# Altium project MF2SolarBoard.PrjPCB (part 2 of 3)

## Sheet DCPower.SchDoc
size B; SheetNumber: 2; nhSheetName: DC Power (PV)
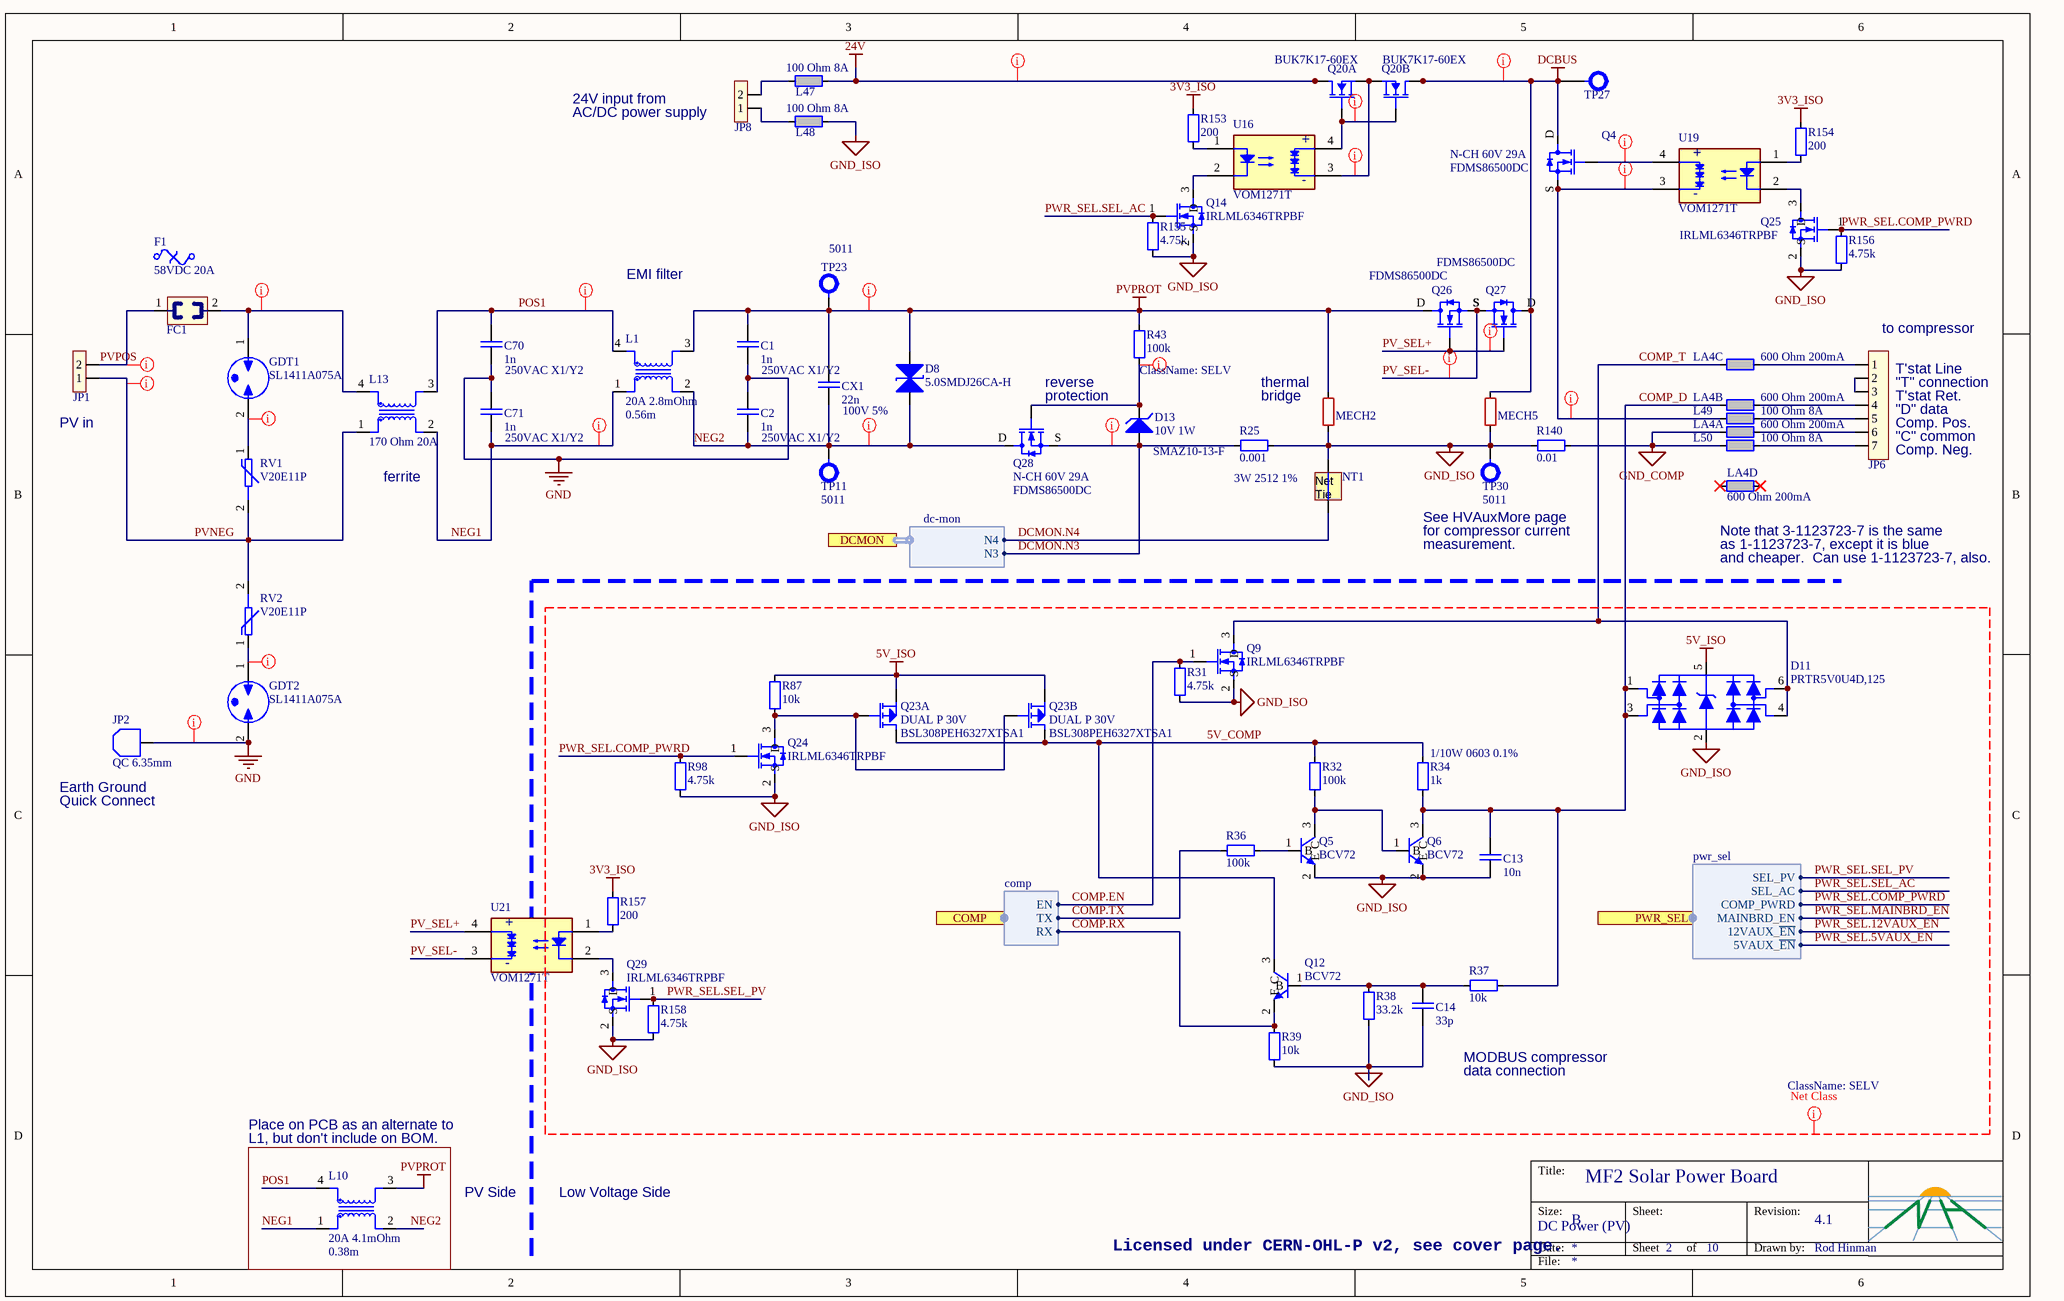
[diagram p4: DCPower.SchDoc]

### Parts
C1  250VAC X1/Y2  value_text: 1n  [CAPC4720X22N]
C2  250VAC X1/Y2  value_text: 1n  [CAPC4720X22N]
C13  value_text: 10n  [CAPC1608X09N[0603]]  (hidden comment: 50V C0G 0603)
C14  value_text: 33p  [CAPC1608X09N[0603]]  (hidden comment: 50V C0G 0603)
C70  250VAC X1/Y2  value_text: 1n  [CAPC4720X22N]
C71  250VAC X1/Y2  value_text: 1n  [CAPC4720X22N]
CX1  100V 5%  value_text: 22n  [CAPC3216X100]
D8  manufacturer_pn: 5.0SMDJ26CA-H  [DO-214AB_SMC_BIDIR]  (hidden comment: TVS)
D11  manufacturer_pn: PRTR5V0U4D,125  [SOT23-6]  (hidden comment: TVS)
D13  10V 1W  manufacturer_pn: SMAZ10-13-F  [DO-214AC]
F1  58VDC 20A  [FUSE_MINI_ATO_20A]  (mechanical)
FC1  MINI  [KEYSTONE_3568]  (value not drawn)
GDT1  manufacturer_pn: SL1411A075A  [LITTELFUSE_SL1411A]  (hidden comment: 75Vdc breakdown)
GDT2  manufacturer_pn: SL1411A075A  [LITTELFUSE_SL1411A]  (hidden comment: 75Vdc breakdown)
JP1  JST VL  [JST_B02P-VL]  (value not drawn)
JP2  QC 6.35mm  [AMP_63849-1]
JP6  1x7 3.96mm blue  [AMP_1-1123723-7]  (value not drawn)
JP8  1x2 3.96mm  [AMP_1-1123723-2]  (value not drawn)
L1  20A 2.8mOhm  value_text: 0.56m  [WURTH_S14100038]
L10  20A 4.1mOhm  value_text: 0.38m  [PULSE_HCCI-80]
L13  170 Ohm 20A  [LAIRD_CM3443Z171R-10]
L47  100 Ohm 8A  [INDC4532X17N[1812]]
L48  100 Ohm 8A  [INDC4532X17N[1812]]
L49  100 Ohm 8A  [INDC4532X17N[1812]]
L50  100 Ohm 8A  [INDC4532X17N[1812]]
LA4  600 Ohm 200mA  [FERCAV80P320X160X70-4]  (parts A,B,C,D of 4)
MECH2  10C/W  [RESC2012X06N[0805]]  (value not drawn)
MECH5  10C/W  [RESC2012X06N[0805]]  (value not drawn)
NT1  Net Tie  [NETTIE1608X05AN[0603]]  (value not drawn)  (net tie, no BOM)
Q4  N-CH 60V 29A  manufacturer_pn: FDMS86500DC  [SOIC-8 PPAK]
Q5  manufacturer_pn: BCV72  [SOT23-3]  (hidden comment: 60V 300mA)
Q6  manufacturer_pn: BCV72  [SOT23-3]  (hidden comment: 60V 300mA)
Q9  manufacturer_pn: IRLML6346TRPBF  [SOT23-3]  (hidden comment: N-CH 30V 3.4A)
Q12  manufacturer_pn: BCV72  [SOT23-3]  (hidden comment: 60V 300mA)
Q14  manufacturer_pn: IRLML6346TRPBF  [SOT23-3]  (hidden comment: N-CH 30V 3.4A)
Q20  manufacturer_pn: BUK7K17-60EX  [SOT1205_LFPAK56D]  (hidden comment: N-CH 60V 30A)  (parts A,B of 2)
Q23  DUAL P 30V  manufacturer_pn: BSL308PEH6327XTSA1  [SOT_23_6]  (parts A,B of 2)
Q24  manufacturer_pn: IRLML6346TRPBF  [SOT23-3]  (hidden comment: N-CH 30V 3.4A)
Q25  manufacturer_pn: IRLML6346TRPBF  [SOT23-3]  (hidden comment: N-CH 30V 3.4A)
Q26  manufacturer_pn: FDMS86500DC  [SOIC-8 PPAK]  (hidden comment: N-CH 60V 29A)
Q27  manufacturer_pn: FDMS86500DC  [SOIC-8 PPAK]  (hidden comment: N-CH 60V 29A)
Q28  N-CH 60V 29A  manufacturer_pn: FDMS86500DC  [SOIC-8 PPAK]
Q29  manufacturer_pn: IRLML6346TRPBF  [SOT23-3]  (hidden comment: N-CH 30V 3.4A)
R25  3W 2512 1%  value_text: 0.001  [RESC6534X70[2512]_mOhm]
R31  value_text: 4.75k  [RESC1608X05AN[0603]]  (hidden comment: 1/10W 0603 1%)
R32  value_text: 100k  [RESC1608X05AN[0603]]  (hidden comment: 1/10W 0603 1%)
R34  1/10W 0603 0.1%  value_text: 1k  [RESC1608X05AN[0603]]
R36  value_text: 100k  [RESC1608X05AN[0603]]  (hidden comment: 1/10W 0603 1%)
R37  value_text: 10k  [RESC1608X05AN[0603]]  (hidden comment: 1/10W 0603 1%)
R38  value_text: 33.2k  [RESC1608X05AN[0603]]  (hidden comment: 1/10W 0603 1%)
R39  value_text: 10k  [RESC1608X05AN[0603]]  (hidden comment: 1/10W 0603 1%)
R43  value_text: 100k  [RESC1608X05AN[0603]]  (hidden comment: 1/10W 0603 1%)
R87  value_text: 10k  [RESC1608X05AN[0603]]  (hidden comment: 1/10W 0603 1%)
R98  value_text: 4.75k  [RESC1608X05AN[0603]]  (hidden comment: 1/10W 0603 1%)
R140  value_text: 0.01  [RESC6534X70[2512]]  (hidden comment: 3W 2512 1%)
R153  value_text: 200  [RESC1608X05AN[0603]]  (hidden comment: 1/10W 0603 1%)
R154  value_text: 200  [RESC1608X05AN[0603]]  (hidden comment: 1/10W 0603 1%)
R155  value_text: 4.75k  [RESC1608X05AN[0603]]  (hidden comment: 1/10W 0603 1%)
R156  value_text: 4.75k  [RESC1608X05AN[0603]]  (hidden comment: 1/10W 0603 1%)
R157  value_text: 200  [RESC1608X05AN[0603]]  (hidden comment: 1/10W 0603 1%)
R158  value_text: 4.75k  [RESC1608X05AN[0603]]  (hidden comment: 1/10W 0603 1%)
RV1  manufacturer_pn: V20E11P  [LITTELFUSE_ULTRAMOV_20MM]  (hidden comment: 11VAC 14VDC MWV)
RV2  manufacturer_pn: V20E11P  [LITTELFUSE_ULTRAMOV_20MM]  (hidden comment: 11VAC 14VDC MWV)
TP11  manufacturer_pn: 5011  [KEYSTONE_5011]  (hidden comment: TP BLK)
TP23  manufacturer_pn: 5011  [KEYSTONE_5011]  (hidden comment: TP BLK)
TP27  TP TH  0.78mm  [TP_TH078H127P]  (value not drawn)  (no BOM)
TP30  manufacturer_pn: 5011  [KEYSTONE_5011]  (hidden comment: TP BLK)
U16  manufacturer_pn: VOM1271T  [VISHAY_SOP-4]  (hidden comment: PV Out)
U19  manufacturer_pn: VOM1271T  [VISHAY_SOP-4]  (hidden comment: PV Out)
U21  manufacturer_pn: VOM1271T  [VISHAY_SOP-4]  (hidden comment: PV Out)

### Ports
COMP (harness comp), DCMON (harness dc-mon), PWR_SEL (harness pwr_sel)

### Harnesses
comp: TX, RX, EN
dc-mon: N4, N3
pwr_sel: SEL_PV, SEL_AC, COMP_PWRD, 12VAUX_~{EN}, 5VAUX_~{EN}, MAINBRD_EN

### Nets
3V3_ISO: R153.2 R154.2 R157.2
5V_ISO: D11.5(VCC) Q23.2(S2) Q23.5(S1) R87.2
24V: L47.1 Q20.7(D1) Q20.8(D1)
DCBUS: MECH5.1 Q4.D Q20.5(D2) Q20.6(D2) Q27.D TP27.1
GND: C1.2 C2.1 C70.2 C71.1 GDT2.2 JP2.1
GND_COMP: L50.1 LA4.1 R140.2
GND_ISO: C13.2 C14.2 D11.2(GND) L48.1 MECH2.2 MECH5.2 NT1.2 Q5.2(E) Q6.2(E) Q9.2(S) Q14.2(S) Q24.2(S) Q25.2(S) Q29.2(S) R25.2 R31.2 R38.2 R39.2 R98.2 R140.1 R155.1 R156.1 R158.1 TP30.1
PVPROT: C1.1 CX1.1 D8.2 L1.3 L10.3 MECH2.1 Q26.D R43.2 TP23.1
5V_COMP: Q12.3(C) Q23.4(D2) Q23.6(D1) R32.1 R34.1
COMP.EN: Q9.1(G) R31.1 ; port COMP.EN
COMP.RX: Q12.2(E) R39.1 ; port COMP.RX
COMP.TX: R36.1 ; port COMP.TX
COMP_D: C13.1 D11.1(IO1) D11.3(IO2) LA4.2 Q6.3(C) R34.2 R37.2
COMP_T: D11.4(IO3) D11.6(IO4) LA4.3 Q9.3(D)
DCMON.N3: D13.A Q28.S R25.1 ; port DCMON.N3
DCMON.N4: NT1.1 ; port DCMON.N4
NEG1: C71.2 L1.1 L10.1 L13.2
NEG2: C2.2 CX1.2 D8.1 L1.2 L10.2 Q28.D TP11.1
POS1: C70.1 L1.4 L10.4 L13.3
PV_SEL+: Q26.G Q27.G U21.4(+)
PV_SEL-: Q26.S Q27.S U21.3(-)
PVNEG: JP1.1 L13.1 RV1.2 RV2.2
PVPOS: FC1.1 JP1.2
PWR_SEL.COMP_PWRD: Q24.1(G) Q25.1(G) R98.1 R156.2 ; port PWR_SEL.COMP_PWRD
PWR_SEL.SEL_AC: Q14.1(G) R155.2 ; port PWR_SEL.SEL_AC
PWR_SEL.SEL_PV: Q29.1(G) R158.2 ; port PWR_SEL.SEL_PV
NetC14_1: C14.1 Q12.1(B) R37.1 R38.1
NetD13_K: D13.K Q28.G R43.1
NetFC1_2: FC1.2 GDT1.1 L13.4
NetGDT1_2: GDT1.2 RV1.1
NetGDT2_1: GDT2.1 RV2.1
NetJP6_1: JP6.1 LA4.6
NetJP6_2: JP6.2 JP6.3
NetJP6_4: JP6.4 LA4.7
NetJP6_5: JP6.5 L49.2
NetJP6_6: JP6.6 LA4.8
NetJP6_7: JP6.7 L50.2
NetJP8_1: JP8.1 L48.2
NetJP8_2: JP8.2 L47.2
NetL49_1: L49.1 Q4.S U19.3(-)
NetQ4_G: Q4.G U19.4(+)
NetQ5_1: Q5.1(B) R36.2
NetQ5_3: Q5.3(C) Q6.1(B) R32.2
NetQ14_3: Q14.3(D) U16.2(Cathode)
NetQ20_1: Q20.1(S1) Q20.3(S2) U16.3(-)
NetQ20_2: Q20.2(G1) Q20.4(G2) U16.4(+)
NetQ23_1: Q23.1(G1) Q23.3(G2) Q24.3(D) R87.1
NetQ25_3: Q25.3(D) U19.2(Cathode)
NetQ29_3: Q29.3(D) U21.2(Cathode)
NetR153_1: R153.1 U16.1(Anode)
NetR154_1: R154.1 U19.1(Anode)
NetR157_1: R157.1 U21.1(Anode)

Not connected (* = marked no-connect by the designer): LA4 4* 5*

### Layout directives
net class PVPOS: 24V, DCBUS, NetFC1_2, NetGDT1_2, NetL49_1, NetQ4_G, NetQ20_1, NetQ20_2, POS1, PV_SEL+, PV_SEL-, PVPOS, PVPROT
net class SELV: 3V3_ISO, 5V_COMP, 5V_ISO, COMP.EN, COMP.RX, COMP.TX, DCMON.N3, GND_ISO, NEG1, NEG2, NetD13_K, NetGDT2_1, PVNEG, PWR_SEL.5VAUX_~{EN}, PWR_SEL.12VAUX_~{EN}, PWR_SEL.COMP_PWRD, PWR_SEL.MAINBRD_EN, PWR_SEL.SEL_AC, PWR_SEL.SEL_PV
net class Earth: GND

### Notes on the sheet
- 24V input from
- (near JP8) AC/DC power supply
- EMI filter
- (near JP6) to compressor
- (near JP6) T'stat Line
- (near JP1) PV in
- (near Q28) reverse
- (near Q28) protection
- (near MECH2) thermal
- (near MECH2) bridge
- (near JP6) T'stat Ret.
- (near JP6) Comp. Pos.
- (near JP6) "C" common
- (near JP6) "T" connection
- (near JP6) "D" data
- (near L13) ferrite
- (near JP6) Comp. Neg.
- See HVAuxMore page
- for compressor current
- measurement.
- (near LA4) Note that 3-1123723-7 is the same
- (near LA4) as 1-1123723-7, except it is blue
- and cheaper.  Can use 1-1123723-7, also.
- (near JP2) Earth Ground
- (near JP2) Quick Connect
- MODBUS compressor
- data connection
- Place on PCB as an alternate to
- (near L10) L1, but don't include on BOM.
- PV Side
- Low Voltage Side
- Licensed under CERN-OHL-P v2, see cover page.

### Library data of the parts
C1 C2 C70 C71 = CAP-00055: CAP CER 1000PF 250VAC X7R 1808; manufacturer: Johanson Dielectrics Inc.; manufacturer_pn: 502R29W102KV3E-****-SC; id: 148102; value: 1E-9; Key Parameters: X1/Y2 rating required
C13 = CAP-00027: 10000pF 50V Ceramic Capacitor C0G, NP0 0603 (1608 Metric) 0.063" L x 0.031" W (1.60mm x 0.80mm); manufacturer: Murata Electronics North America; manufacturer_pn: GRM1885C1H103JA01D; id: 137118; value: 1E-8; Key Parameters: V >= 6.3V
C14 = CAP-00043: 33pF 50V Ceramic Capacitor C0G, NP0 0603 (1608 Metric) 0.063" L x 0.031" W (1.60mm x 0.80mm); manufacturer: Murata Electronics North America; manufacturer_pn: GRM1885C1H330JA01D; id: 140735; value: 3.3E-11; Key Parameters: v >= 6.3V
CX1 = CAP-00054: CAP CER 0.022UF 100V X7R 1206; manufacturer: Kemet; manufacturer_pn: C1206C223J1RACTU; id: 148096; value: 2.2E-8
D8 = DIO-00038: TVS DIODE 26VWM 42.1VC SMD; manufacturer: Bourns Inc.; id: 193256
D11 = DIO-00000: TVS DIODE 6TSOP; manufacturer: Nexperia USA Inc.; id: 136479
D13 = DIO-00010: Zener Diode 10V 1W ±5% Surface Mount SMA; manufacturer: Diodes Incorporated; id: 137140
F1 = FUSE-00009: FUSE AUTO 20A 58VDC BLADE MINI; manufacturer_pn: 0997020.WXN; manufacturer: Littelfuse Inc.; id: 169759
FC1 = CONN-00117: FUSE HOLDER BLADE 500V 20A PCB; manufacturer_pn: 3568; manufacturer: Keystone Electronics; id: 169758
GDT1 GDT2 = PROT-00004: GDT 75V 10KA THROUGH HOLE; manufacturer: Littelfuse Inc.; id: 147370; value: 75
JP1 = CONN-00118: 2 Positions Header Connector 0.244" (6.20mm) Through Hole Tin; manufacturer_pn: B02P-VL; manufacturer: JST Sales America Inc.; id: 170439
JP2 = CONN-00071: 0.250" (6.35mm) Quick Connect Male Solder Connector Non-Insulated; manufacturer: TE Connectivity AMP Connectors; manufacturer_pn: 63849-1; id: 140464
JP6 = CONN-00087: 7 Positions Header, Unshrouded Connector 0.156" (3.96mm) Through Hole Tin; manufacturer: TE Connectivity AMP Connectors; manufacturer_pn: 3-1123723-7; id: 147885
JP8 = CONN-00067: 2 Positions Header, Unshrouded Connector 0.156" (3.96mm) Through Hole Tin (blue); manufacturer_pn: 3-1123723-2; manufacturer: TE Connectivity AMP Connectors; id: 140460
L1 = IND-00021: 560µH @ 10kHz 2 Line Common Mode Choke Through Hole 20A DCR 2.8 mOhm; manufacturer: Wurth Electronics Inc; manufacturer_pn: S14100038; id: 169932; value: 0.00056
L10 = IND-00022: 2 Line Common Mode Choke Surface Mount 20A DCR 4.1 mOhm; manufacturer_pn: PG1265NL; manufacturer: Pulse Electronics Corporation; id: 169933; value: 0.00038
L13 = FER-00010: 2 Line Common Mode Choke Surface Mount 170 Ohm @ 100MHz 20A DCR 1 mOhm; manufacturer: Laird Technologies EMI; manufacturer_pn: CM3440Z171R-10; value_text: 170; id: 169934; value: 170
L47-L50 = FER-00011: FERRITE BEAD 100 OHM 1812 1LN 10mohm; manufacturer_pn: HI1812V101R-10; manufacturer: Laird Technologies EMI; value_text: 100; id: 169937; value: 100
LA4 = FER-00009: FERRITE BEAD 600 OHM 1206 4LN; manufacturer_pn: BK32164S601-T; manufacturer: Taiyo Yuden; id: 162218; value: 600
MECH2 MECH5 = MECH-00031: Heat Sink Aluminum Nitride Ceramic Heat Spreader Q-Bridge; manufacturer_pn: QB0805A40WYTD; manufacturer: American Technical Ceramics; id: 197164
NT1 = NOBOM-00005: Net tie 0603; manufacturer: New Horizons; id: 137435
Q4 Q26-Q28 = FET-00018: N-Channel 60V 29A (Ta), 108A (Tc) 3.2W (Ta), 125W (Tc) Surface Mount Dual Cool™56; manufacturer: ON Semiconductor; id: 193254
Q5 Q6 Q12 = BJT-00001: Bipolar (BJT) Transistor NPN 60V 500mA 350mW Surface Mount SOT-23-3; manufacturer: ON Semiconductor; id: 145546
Q9 Q14 Q24 Q25 Q29 = FET-00002: MOSFET N-CH 30V 3.4A SOT23; manufacturer: Infineon Technologies; id: 137229
Q20 = FET-00017: Mosfet Array 2 N-Channel (Dual) 60V 30A 53W Surface Mount LFPAK56D; manufacturer: Nexperia USA Inc.; id: 193253
Q23 = FET-00023: Mosfet Array 2 P-Channel (Dual) 30V 2A 500mW Surface Mount PG-TSOP-6-6; manufacturer: Infineon Technologies; id: 297421
R25 = RES-00044: RES SMD 0.001 OHM 1% 3W 2512; manufacturer: Bourns Inc.; manufacturer_pn: CRE2512-FZ-R001E-3; id: 138477; value: 0.001
R31 R98 R155 R156 R158 = RES-00013: RES SMD 4.75K OHM 1% 1/10W 0603; manufacturer_pn: ERJ-3EKF4751V; manufacturer: Panasonic Electronic Components; id: 137091; value: 4750; Key Parameters: 5% OK
R32 = RES-00112: 100 kOhms ±1% 0.1W, 1/10W Chip Resistor 0603 (1608 Metric) Automotive AEC-Q200 Thick Film; manufacturer_pn: ERJ-3EKF1003V; manufacturer: Panasonic Electronic Components; id: 185358; value: 100000; Key Parameters: 1% required for R195.  5% OK for others.
R34 = RES-00067: RES SMD 1KOHM 0.1% 1/10W 0603; manufacturer_pn: ERA-3AEB102V; manufacturer: Panasonic Electronic Components; id: 147997; value: 1000; Key Parameters: 0.1% required
R36 R43 = RES-00112: 100 kOhms ±1% 0.1W, 1/10W Chip Resistor 0603 (1608 Metric) Automotive AEC-Q200 Thick Film; manufacturer_pn: ERJ-3EKF1003V; manufacturer: Panasonic Electronic Components; id: 185358; value: 100000; Key Parameters: 1% required
R37 R39 = RES-00107: 10 kOhms ±1% 0.1W, 1/10W Chip Resistor 0603 (1608 Metric) Automotive AEC-Q200 Thick Film; manufacturer_pn: ERJ-3EKF1002V; manufacturer: Panasonic Electronic Components; id: 182861; value: 10000; Key Parameters: 1% required
R38 = RES-00027: RES SMD 33.2K OHM 1% 1/10W 0603; manufacturer_pn: ERJ-3EKF3322V; manufacturer: Panasonic Electronic Components; id: 137105; value: 33200; Key Parameters: 5% OK
R87 = RES-00107: 10 kOhms ±1% 0.1W, 1/10W Chip Resistor 0603 (1608 Metric) Automotive AEC-Q200 Thick Film; manufacturer: Panasonic Electronic Components; manufacturer_pn: ERJ-3EKF1002V; id: 182861; value: 10000; Key Parameters: 1% required
R140 = RES-00036: RES SMD 0.01 OHM 1% 3W 2512; manufacturer_pn: CRA2512-FZ-R010ELF; manufacturer: Bourns Inc.; id: 137235; value: 0.01; Key Parameters: 1% required
R153 R154 R157 = RES-00019: RES SMD 200 OHM 1% 1/10W 0603; manufacturer_pn: ERJ-3EKF2000V; manufacturer: Panasonic Electronic Components; id: 137097; value: 200; Key Parameters: 5% OK
RV1 RV2 = PROT-00005: VARISTOR 18V 8KA DISC 20MM; manufacturer: Littelfuse Inc.; id: 147371; value: 11
TP11 TP23 TP30 = CONN-00028: TEST POINT PC MULTI PURPOSE BLK; manufacturer: Keystone Electronics; id: 137441
TP27 = NOBOM-00007: Test point, TH, 0.78mm (30mil) hole, 1.27mm (50 mil) pad; manufacturer: New Horizons; id: 137437
U16 U19 U21 = ICXCV-00017: Optoisolator Photovoltaic Output 4500Vrms 1 Channel 4-SOP (2.54mm); manufacturer: Vishay Semiconductor Opto Division; id: 171983

## Sheet ACProtection.SchDoc
size B; SheetNumber: 5; nhSheetName: AC Protection Ctl
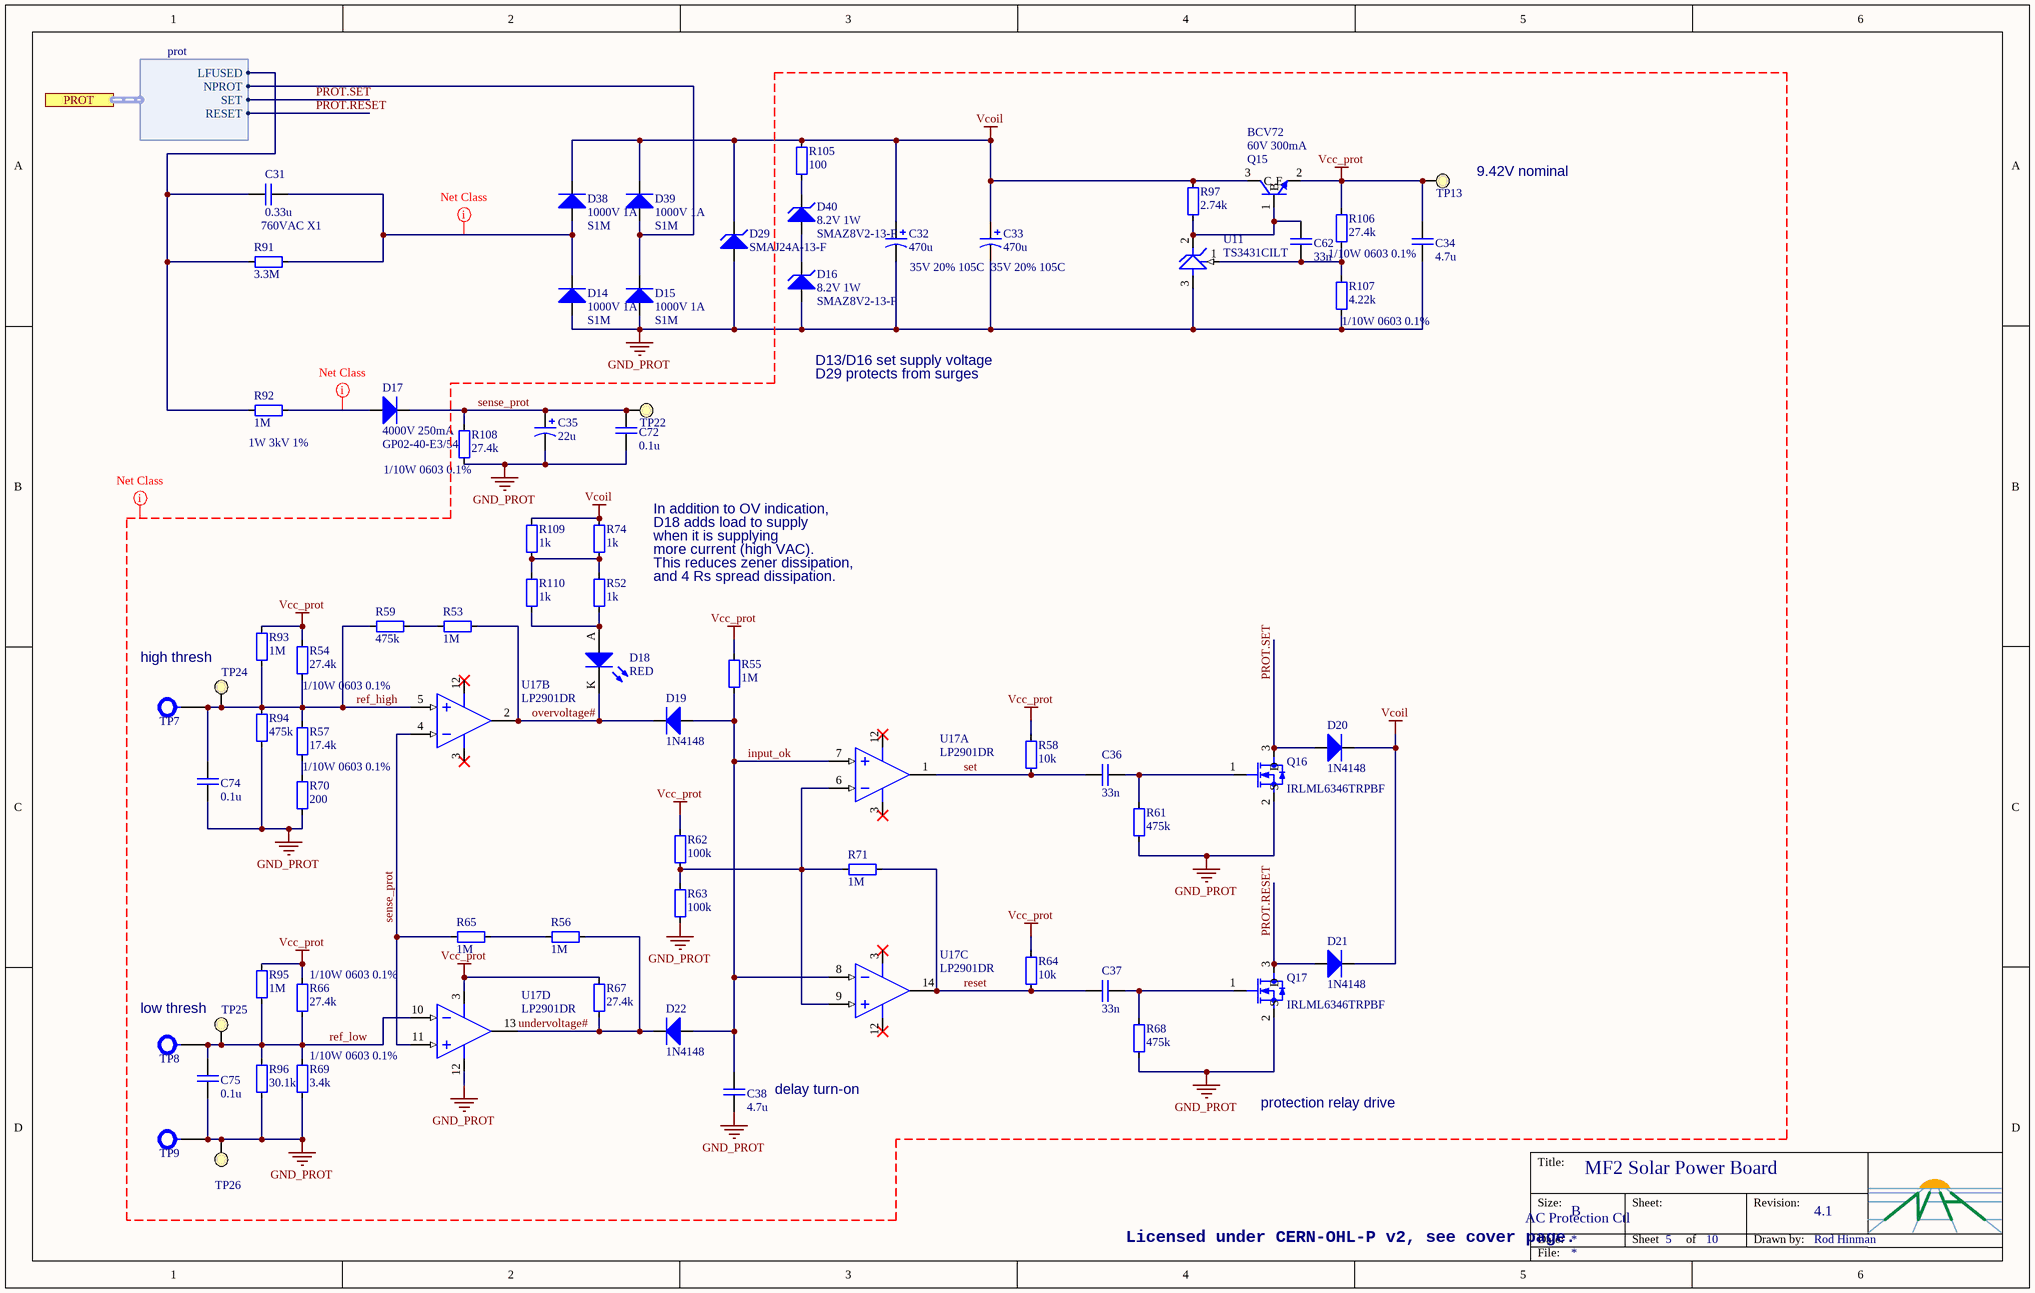
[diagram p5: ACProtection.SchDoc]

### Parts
C31  760VAC X1  value_text: 0.33u  [KEMET_PHE845VF6330MR06L2]
C32  35V 20% 105C  value_text: 470u  [CAP_RB5/10MMX20MM]
C33  35V 20% 105C  value_text: 470u  [CAP_RB5/10MMX20MM]
C34  value_text: 4.7u  [CAPC1608X09N[0603]]  (hidden comment: 25V X6S 0603)
C35  value_text: 22u  [CAP_ALUM_SIZE-SVPF-B6]  (hidden comment: 35V 20% 1 ohm)
C36  value_text: 33n  [CAPC1608X09N[0603]]  (hidden comment: 50V X7R 0603)
C37  value_text: 33n  [CAPC1608X09N[0603]]  (hidden comment: 50V X7R 0603)
C38  value_text: 4.7u  [CAPC1608X09N[0603]]  (hidden comment: 25V X6S 0603)
C62  value_text: 33n  [CAPC1608X09N[0603]]  (hidden comment: 50V X7R 0603)
C72  value_text: 0.1u  [CAPC1608X09N[0603]]  (hidden comment: 50V X7R 0603)
C74  value_text: 0.1u  [CAPC1608X09N[0603]]  (hidden comment: 50V X7R 0603)
C75  value_text: 0.1u  [CAPC1608X09N[0603]]  (hidden comment: 50V X7R 0603)
D14  1000V 1A  manufacturer_pn: S1M  [DO-214AC]
D15  1000V 1A  manufacturer_pn: S1M  [DO-214AC]
D16  8.2V 1W  manufacturer_pn: SMAZ8V2-13-F  [DO-214AC]
D17  4000V 250mA  manufacturer_pn: GP02-40-E3/54  [DO-204AL[DO-41]]
D18  RED  [LEDC1608X06NRED,0603,]
D19  1N4148  [SOD-123]
D20  1N4148  [SOD-123]
D21  1N4148  [SOD-123]
D22  1N4148  [SOD-123]
D29  manufacturer_pn: SMAJ24A-13-F  [DO-214AC]  (hidden comment: 24WVM)
D38  1000V 1A  manufacturer_pn: S1M  [DO-214AC]
D39  1000V 1A  manufacturer_pn: S1M  [DO-214AC]
D40  8.2V 1W  manufacturer_pn: SMAZ8V2-13-F  [DO-214AC]
Q15  60V 300mA  manufacturer_pn: BCV72  [SOT23-3]
Q16  manufacturer_pn: IRLML6346TRPBF  [SOT23-3]  (hidden comment: N-CH 30V 3.4A)
Q17  manufacturer_pn: IRLML6346TRPBF  [SOT23-3]  (hidden comment: N-CH 30V 3.4A)
R52  value_text: 1k  [RESC1608X05AN[0603]]  (hidden comment: 1/10W 0603 1%)
R53  value_text: 1M  [RESC1608X05AN[0603]]  (hidden comment: 1/10W 0603 1%)
R54  1/10W 0603 0.1%  value_text: 27.4k  [RESC1608X05AN[0603]]
R55  value_text: 1M  [RESC1608X05AN[0603]]  (hidden comment: 1/10W 0603 1%)
R56  value_text: 1M  [RESC1608X05AN[0603]]  (hidden comment: 1/10W 0603 1%)
R57  1/10W 0603 0.1%  value_text: 17.4k  [RESC1608X05AN[0603]]
R58  value_text: 10k  [RESC1608X05AN[0603]]  (hidden comment: 1/10W 0603 1%)
R59  value_text: 475k  [RESC1608X05AN[0603]]  (hidden comment: 1/10W 0603 1%)
R61  value_text: 475k  [RESC1608X05AN[0603]]  (hidden comment: 1/10W 0603 1%)
R62  value_text: 100k  [RESC1608X05AN[0603]]  (hidden comment: 1/10W 0603 1%)
R63  value_text: 100k  [RESC1608X05AN[0603]]  (hidden comment: 1/10W 0603 1%)
R64  value_text: 10k  [RESC1608X05AN[0603]]  (hidden comment: 1/10W 0603 1%)
R65  value_text: 1M  [RESC1608X05AN[0603]]  (hidden comment: 1/10W 0603 1%)
R66  1/10W 0603 0.1%  value_text: 27.4k  [RESC1608X05AN[0603]]
R67  value_text: 27.4k  [RESC1608X05AN[0603]]  (hidden comment: 1/10W 0603 0.1%)
R68  value_text: 475k  [RESC1608X05AN[0603]]  (hidden comment: 1/10W 0603 1%)
R69  1/10W 0603 0.1%  value_text: 3.4k  [RESC1608X05AN[0603]]
R70  value_text: 200  [RESC1608X05AN[0603]]  (hidden comment: 1/10W 0603 1%)
R71  value_text: 1M  [RESC1608X05AN[0603]]  (hidden comment: 1/10W 0603 1%)
R74  value_text: 1k  [RESC1608X05AN[0603]]  (hidden comment: 1/10W 0603 1%)
R91  value_text: 3.3M  [RESC5025X60,2010,]  (hidden comment: 0.5W 2010 1%)
R92  1W 3kV 1%  value_text: 1M  [RESC6534X70[2512]]
R93  value_text: 1M  [RESC1608X05AN[0603]]  (hidden comment: 1/10W 0603 1%)
R94  value_text: 475k  [RESC1608X05AN[0603]]  (hidden comment: 1/10W 0603 1%)
R95  value_text: 1M  [RESC1608X05AN[0603]]  (hidden comment: 1/10W 0603 1%)
R96  value_text: 30.1k  [RESC1608X05AN[0603]]  (hidden comment: 1/10W 0603 1%)
R97  value_text: 2.74k  [RESC1608X05AN[0603]]  (hidden comment: 1/10W 0603 1%)
R105  value_text: 100  [RESC6534X70[2512]]  (hidden comment: 1W 2512 5%)
R106  1/10W 0603 0.1%  value_text: 27.4k  [RESC1608X05AN[0603]]
R107  1/10W 0603 0.1%  value_text: 4.22k  [RESC1608X05AN[0603]]
R108  1/10W 0603 0.1%  value_text: 27.4k  [RESC1608X05AN[0603]]
R109  value_text: 1k  [RESC1608X05AN[0603]]  (hidden comment: 1/10W 0603 1%)
R110  value_text: 1k  [RESC1608X05AN[0603]]  (hidden comment: 1/10W 0603 1%)
TP7  TP TH  0.78mm  [TP_TH078H127P]  (value not drawn)  (no BOM)
TP8  TP TH  0.78mm  [TP_TH078H127P]  (value not drawn)  (no BOM)
TP9  TP TH  0.78mm  [TP_TH078H127P]  (value not drawn)  (no BOM)
TP13  TP SMD 1.5mm  [TP_SMD_Ø1.5mm]  (value not drawn)  (no BOM)
TP22  TP SMD 1.5mm  [TP_SMD_Ø1.5mm]  (value not drawn)  (no BOM)
TP24  TP SMD 1.5mm  [TP_SMD_Ø1.5mm]  (value not drawn)  (no BOM)
TP25  TP SMD 1.5mm  [TP_SMD_Ø1.5mm]  (value not drawn)  (no BOM)
TP26  TP SMD 1.5mm  [TP_SMD_Ø1.5mm]  (value not drawn)  (no BOM)
U11  manufacturer_pn: TS3431CILT  [SOT_23_3]  (hidden comment: TS3431)
U17  LP2901DR  [SOIC-14]  (parts A,B,C,D of 4)

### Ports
PROT (harness prot)

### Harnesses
prot: LFUSED, NPROT, SET, RESET

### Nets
GND_PROT: C32.- C33.- C34.2 C35.- C38.2 C72.2 C74.2 C75.2 D14.A D15.A D16.A D29.A Q16.2(S) Q17.2(S) R61.1 R63.1 R68.1 R69.2 R70.2 R94.2 R96.2 R107.2 R108.2 TP9.1 TP26.1 U11.3(A) U17.12(V-)
Vcc_prot: C34.1 Q15.2(E) R54.1 R55.2 R58.2 R62.2 R64.2 R66.1 R67.2 R93.1 R95.1 R106.1 TP13.1 U17.3(V+)
Vcoil: C32.+ C33.+ D20.K D21.K D29.K D38.K D39.K Q15.3(C) R74.2 R97.2 R105.1 R109.2
input_ok: C38.1 D19.A D22.A R55.1 U17.7(IN1+) U17.8(IN3-)
overvoltage#: D18.K D19.K R53.1 U17.2(OUT2)
PROT.LFUSED: C31.1 R91.1 R92.1 ; port PROT.LFUSED
PROT.NPROT: D15.K D39.A ; port PROT.NPROT
PROT.RESET: D21.A Q17.3(D) ; port PROT.RESET
PROT.SET: D20.A Q16.3(D) ; port PROT.SET
ref_high: C74.1 R54.2 R57.2 R59.2 R93.2 R94.1 TP7.1 TP24.1 U17.5(IN2+)
ref_low: C75.1 R66.2 R69.1 R95.2 R96.1 TP8.1 TP25.1 U17.10(IN4-)
reset: C37.2 R64.1 R71.1 U17.14(OUT3)
sense_prot: C35.+ C72.1 D17.K R65.2 R108.1 TP22.1 U17.4(IN2-) U17.11(IN4+)
set: C36.2 R58.1 U17.1(OUT1)
undervoltage#: D22.K R56.1 R67.1 U17.13(OUT4)
NetC31_2: C31.2 D14.K D38.A R91.2
NetC36_1: C36.1 Q16.1(G) R61.2
NetC37_1: C37.1 Q17.1(G) R68.2
NetC62_1: C62.1 Q15.1(B) R97.1 U11.2(K)
NetC62_2: C62.2 R106.2 R107.1 U11.1(VREF)
NetD16_K: D16.K D40.A
NetD17_A: D17.A R92.2
NetD18_A: D18.A R52.1 R110.1
NetD40_K: D40.K R105.2
NetR52_2: R52.2 R74.1 R109.1 R110.2
NetR53_2: R53.2 R59.1
NetR56_2: R56.2 R65.1
NetR57_1: R57.1 R70.1
NetR62_1: R62.1 R63.2 R71.2 U17.6(IN1-) U17.9(IN3+)

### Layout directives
net class ProtCtrl: GND_PROT, input_ok, NetC31_2, overvoltage#, PROT.RESET, PROT.SET, ref_high, ref_low, reset, sense_prot, set, undervoltage#, Vcc_prot, Vcoil
net class LineUnprot: NetD17_A

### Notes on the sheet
- (near TP13) 9.42V nominal
- D13/D16 set supply voltage
- D29 protects from surges
- D18 adds load to supply
- when it is supplying
- more current (high VAC).
- This reduces zener dissipation,
- In addition to OV indication,
- and 4 Rs spread dissipation.
- high thresh
- low thresh
- delay turn-on
- protection relay drive
- Licensed under CERN-OHL-P v2, see cover page.

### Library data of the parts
C31 = CAP-00039: 0.33µF Film Capacitor 760V 1500V (1.5kV) Polypropylene (PP), Metallized Radial 1.240" L x 0.748" W (31.50mm x 19.00mm); manufacturer: Kemet; manufacturer_pn: PHE845VF6330MR06L2; id: 139964; value: 3.3E-7; Key Parameters: X1 rating required
C32 C33 = CAP-00032: 470µF 35V Aluminum Capacitors Radial, Can 2000 Hrs @ 105°C; manufacturer: Kemet; manufacturer_pn: ESH477M035AH3AA; id: 137131; value: 0.00047; Key Parameters: V >= 35V
C34 C38 = CAP-00015: 4.7µF 25V Ceramic Capacitor X6S 0603 (1608 Metric) 0.063" L x 0.031" W (1.60mm x 0.80mm); manufacturer: Murata Electronics North America; manufacturer_pn: GRM188C81E475KE11D; id: 136726; value: 4.7E-6; Key Parameters: V >= 16V
C35 = CAP-00073: 22µF 35V Aluminum Electrolytic Capacitors Radial, Can - SMD 1 Ohm @ 100kHz 2000 Hrs @ 105°C; manufacturer: Kemet; manufacturer_pn: EEV226M035A9DAA; id: 171406; value: 2.2E-5; Key Parameters: V >= 35V
C36 C37 C62 = CAP-00000: 0.033µF 50V Ceramic Capacitor X7R 0603 (1608 Metric) 0.063" L x 0.031" W (1.60mm x 0.80mm); manufacturer: Murata Electronics North America; manufacturer_pn: GRM188R71H333KA61D; id: 136460; value: 3.3E-8; Key Parameters: V >= 16V
C72 C74 C75 = CAP-00001: 0.10µF 50V Ceramic Capacitor X7R 0603 (1608 Metric) 0.063" L x 0.031" W (1.60mm x 0.80mm); manufacturer: Murata Electronics North America; manufacturer_pn: GRM188R71H104KA93D; id: 136482; value: 1E-7; Key Parameters: V >= 25V
D14 D15 D38 D39 = DIO-00009: Diode Standard 1000V (1kV) 1A Surface Mount SMA (DO-214AC); manufacturer: Fairchild Semiconductor; id: 137139
D16 D40 = DIO-00017: Zener Diode 8.2V 1W ±5% Surface Mount SMA; manufacturer: Diodes Incorporated; id: 141314
D17 = DIO-00011: Diode Standard 4000V (4kV) 250mA Through Hole DO-204AL (DO-41); manufacturer: Vishay Semiconductor Diodes Division; id: 137141
D18 = LED-00005: Red 633nm LED Indication - Discrete 2V 0603 (1608 Metric) 28mcd min, 104mcd typ., diffused; manufacturer: OSRAM Opto Semiconductors Inc.; manufacturer_pn: LS Q976-NR-1; id: 137518
D19-D22 = DIO-00004: Diode Standard 100V 150mA Surface Mount SOD-123; manufacturer_pn: 1N4148W-TP; manufacturer: Micro Commercial Co; id: 137134
D29 = DIO-00018: TVS DIODE 24VWM 38.9VC SMA; manufacturer: Diodes Incorporated; id: 145545
Q15 = BJT-00001: as Q5 on sheet DCPower
Q16 Q17 = FET-00002: as Q9 on sheet DCPower
R52 R74 R109 R110 = RES-00113: 1 kOhms ±1% 0.1W, 1/10W Chip Resistor 0603 (1608 Metric) Automotive AEC-Q200 Thick Film; manufacturer: Panasonic Electronic Components; manufacturer_pn: ERJ-3EKF1001V; id: 185365; value: 1000; Key Parameters: 1% required
R53 R55 R56 R65 R71 = RES-00114: 1 MOhms ±1% 0.1W, 1/10W Chip Resistor 0603 (1608 Metric) Automotive AEC-Q200 Thick Film; manufacturer: Panasonic Electronic Components; manufacturer_pn: ERJ-3EKF1004V; id: 185423; value: 1000000; Key Parameters: 5% OK
R54 R66 R67 R106 R108 = RES-00051: RES SMD 27.4KOHM 0.1% 1/10W 0603; manufacturer: Panasonic Electronic Components; manufacturer_pn: ERA-3AEB2742V; id: 141324; value: 27400; Key Parameters: 0.1% required
R57 = RES-00057: 17.4k Ohm ±0.1% 0.1W, 1/10W Chip Resistor 0603 (1608 Metric) Moisture Resistant Thin Film; manufacturer: Yageo; manufacturer_pn: RT0603BRD0717K4L; id: 145543; value: 17400; Key Parameters: 0.1% required
R58 R64 = RES-00107: as R87 on sheet DCPower
R59 R61 R68 = RES-00032: RES SMD 475K OHM 1% 1/10W 0603; manufacturer: Panasonic Electronic Components; manufacturer_pn: ERJ-3EKF4753V; id: 137110; value: 475000; Key Parameters: 1% required
R62 R63 = RES-00112: 100 kOhms ±1% 0.1W, 1/10W Chip Resistor 0603 (1608 Metric) Automotive AEC-Q200 Thick Film; manufacturer: Panasonic Electronic Components; manufacturer_pn: ERJ-3EKF1003V; id: 185358; value: 100000; Key Parameters: 1% required
R69 = RES-00056: 3.4k Ohm ±0.1% 0.1W, 1/10W Chip Resistor 0603 (1608 Metric) Moisture Resistant Thin Film; manufacturer: Yageo; manufacturer_pn: RT0603BRD073K4L; id: 145542; value: 3400; Key Parameters: 0.1% required
R70 = RES-00019: RES SMD 200 OHM 1% 1/10W 0603; manufacturer: Panasonic Electronic Components; manufacturer_pn: ERJ-3EKF2000V; id: 137097; value: 200; Key Parameters: 5% OK
R91 = RES-00125: 3.3 MOhms ±1% 0.5W, 1/2W Chip Resistor 2010 (5025 Metric) High Voltage Thick Film; manufacturer: Bourns Inc.; manufacturer_pn: CHV2010-FX-3304ELF; id: 192299; value: 3300000; Key Parameters: 1% required
R92 = RES-00150: 1 MOhms ±1% 1W Chip Resistor Nonstandard High Voltage Thick Film; manufacturer: Bourns Inc.; manufacturer_pn: CHV2512-FX-1004ELF; id: 245406; value: 1000000; Key Parameters: 1% required
R93 R95 = RES-00114: 1 MOhms ±1% 0.1W, 1/10W Chip Resistor 0603 (1608 Metric) Automotive AEC-Q200 Thick Film; manufacturer_pn: ERJ-3EKF1004V; manufacturer: Panasonic Electronic Components; id: 185423; value: 1000000; Key Parameters: 5% OK
R94 = RES-00032: RES SMD 475K OHM 1% 1/10W 0603; manufacturer_pn: ERJ-3EKF4753V; manufacturer: Panasonic Electronic Components; id: 137110; value: 475000; Key Parameters: 1% required
R96 = RES-00026: RES SMD 30.1K OHM 1% 1/10W 0603; manufacturer_pn: CRCW060330K1FKEA; manufacturer: Vishay Dale; id: 137104; value: 30100
R97 = RES-00055: RES SMD 2.74K OHM 1% 1/10W 0603; manufacturer: Panasonic Electronic Components; manufacturer_pn: ERJ-3EKF2741V; id: 144315; value: 2740; Key Parameters: 1% required
R105 = RES-00098: RES SMD 100 OHM 5% 1W 2512; manufacturer: Panasonic Electronic Components; manufacturer_pn: ERJ-1TYJ101U; id: 171401; value: 100; Key Parameters: 5% OK
R107 = RES-00050: RES SMD 4.22KOHM 0.1% 1/10W 0603; manufacturer: Yageo; manufacturer_pn: RT0603BRD074K22L; id: 141323; value: 4220; Key Parameters: 0.1% required
TP7-TP9 = NOBOM-00007: as TP27 on sheet DCPower
TP13 TP22 TP24-TP26 = NOBOM-00008: Test point, SMD, 1.5mm dia (0.059"); manufacturer: New Horizons; id: 137590
U11 = ICPWR-00010: Shunt Voltage Reference IC 24V ±0.25% 100mA SOT-23-3; manufacturer: STMicroelectronics; id: 138487
U17 = ICANA-00012: Comparator General Purpose CMOS, MOS, Open-Collector 14-SOIC; manufacturer: Texas Instruments; id: 145544

## Sheet ACPower.SchDoc
size B; SheetNumber: 4; nhSheetName: AC Power Input
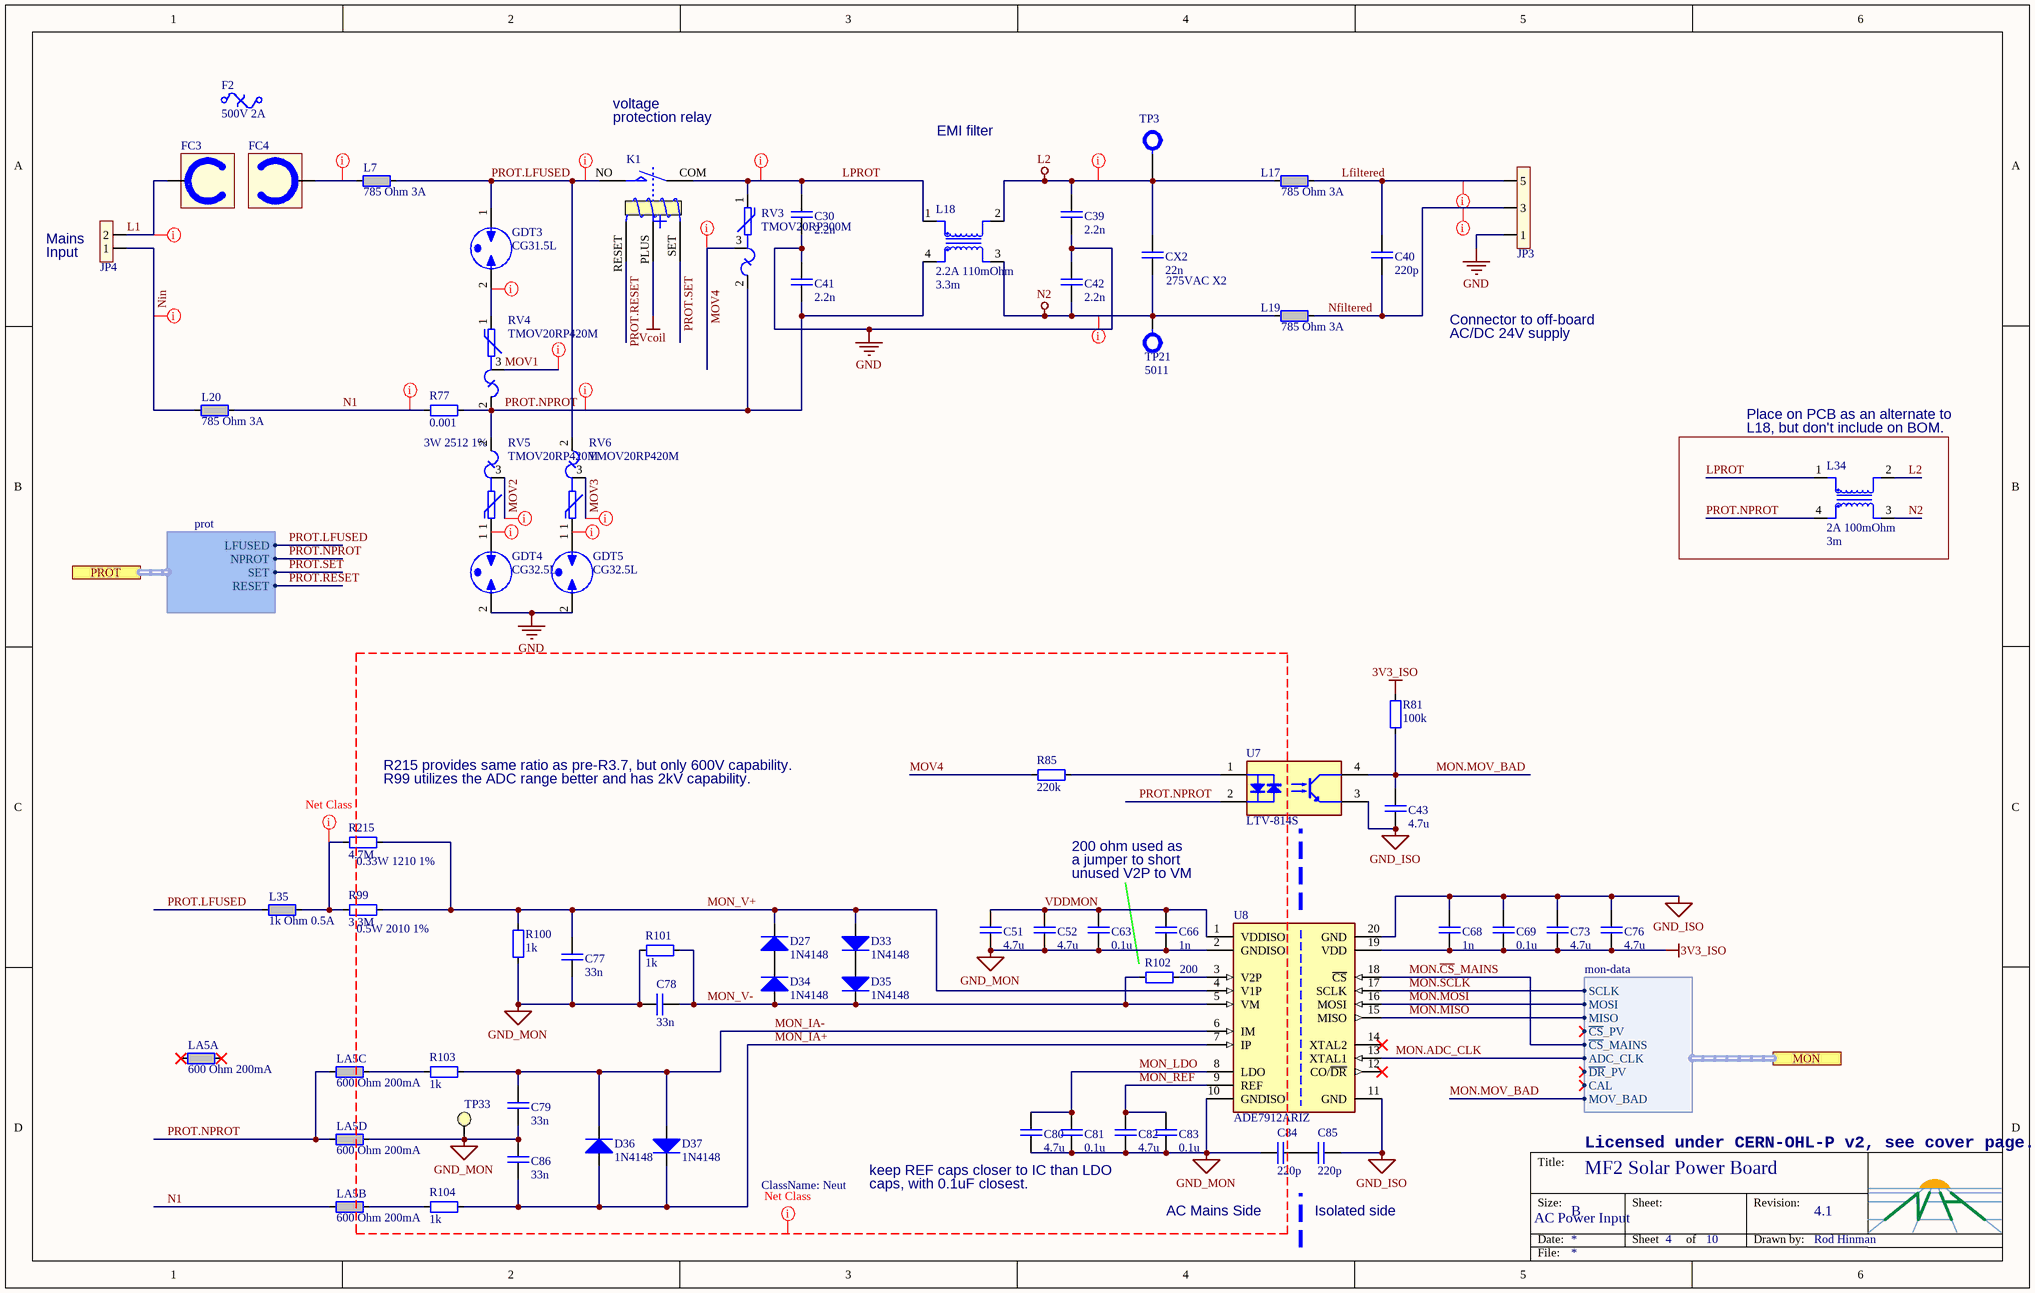
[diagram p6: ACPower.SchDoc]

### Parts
C30  value_text: 2.2n  [CAP_RAD10P_DISC_10x5.5]  (hidden comment: 400VAC X1 Y1)
C39  value_text: 2.2n  [CAP_RAD10P_DISC_10x5.5]  (hidden comment: 400VAC X1 Y1)
C40  value_text: 220p  [CAPC4720X22N]  (hidden comment: 250VAC X1/Y2)
C41  value_text: 2.2n  [CAP_RAD10P_DISC_10x5.5]  (hidden comment: 400VAC X1 Y1)
C42  value_text: 2.2n  [CAP_RAD10P_DISC_10x5.5]  (hidden comment: 400VAC X1 Y1)
C43  value_text: 4.7u  [CAPC1608X09N[0603]]  (hidden comment: 25V X6S 0603)
C51  value_text: 4.7u  [CAPC1608X09N[0603]]  (hidden comment: 25V X6S 0603)
C52  value_text: 4.7u  [CAPC1608X09N[0603]]  (hidden comment: 25V X6S 0603)
C63  value_text: 0.1u  [CAPC1608X09N[0603]]  (hidden comment: 50V X7R 0603)
C66  value_text: 1n  [CAPC1608X09N[0603]]  (hidden comment: 50V C0G 0603)
C68  value_text: 1n  [CAPC1608X09N[0603]]  (hidden comment: 50V C0G 0603)
C69  value_text: 0.1u  [CAPC1608X09N[0603]]  (hidden comment: 50V X7R 0603)
C73  value_text: 4.7u  [CAPC1608X09N[0603]]  (hidden comment: 25V X6S 0603)
C76  value_text: 4.7u  [CAPC1608X09N[0603]]  (hidden comment: 25V X6S 0603)
C77  value_text: 33n  [CAPC1608X09N[0603]]  (hidden comment: 50V X7R 0603)
C78  value_text: 33n  [CAPC1608X09N[0603]]  (hidden comment: 50V X7R 0603)
C79  value_text: 33n  [CAPC1608X09N[0603]]  (hidden comment: 50V X7R 0603)
C80  value_text: 4.7u  [CAPC1608X09N[0603]]  (hidden comment: 25V X6S 0603)
C81  value_text: 0.1u  [CAPC1608X09N[0603]]  (hidden comment: 50V X7R 0603)
C82  value_text: 4.7u  [CAPC1608X09N[0603]]  (hidden comment: 25V X6S 0603)
C83  value_text: 0.1u  [CAPC1608X09N[0603]]  (hidden comment: 50V X7R 0603)
C84  value_text: 220p  [CAPC4720X22N]  (hidden comment: 250VAC X1/Y2)
C85  value_text: 220p  [CAPC4720X22N]  (hidden comment: 250VAC X1/Y2)
C86  value_text: 33n  [CAPC1608X09N[0603]]  (hidden comment: 50V X7R 0603)
CX2  275VAC X2  value_text: 22n  [CAP_RAD15P1805X11]
D27  1N4148  [SOD-123]
D33  1N4148  [SOD-123]
D34  1N4148  [SOD-123]
D35  1N4148  [SOD-123]
D36  1N4148  [SOD-123]
D37  1N4148  [SOD-123]
F2  500V 2A  [FUSE_5X20]  (mechanical)
FC3  5x20mm clip  [SCHURTER_0751.0110]  (value not drawn)
FC4  5x20mm clip  [SCHURTER_0751.0110]  (value not drawn)
GDT3  manufacturer_pn: CG31.5L  [LITTELFUSE_CG3x]  (hidden comment: 1500Vdc breakdown)
GDT4  manufacturer_pn: CG32.5L  [LITTELFUSE_CG3x]  (hidden comment: 2500Vdc breakdown)
GDT5  manufacturer_pn: CG32.5L  [LITTELFUSE_CG3x]  (hidden comment: 2500Vdc breakdown)
JP3  1x5_odd (3.96mm)  [AMP_1-1123724-3]  (value not drawn)
JP4  MLX  [MOLEX_432550059]  (value not drawn)
K1  SPST 12V  [TE_RT1_2COIL_LATCHING]  (value not drawn)
L7  785 Ohm 3A  [INDC4532X17N[1812]]
L17  785 Ohm 3A  [INDC4532X17N[1812]]
L18  2.2A 110mOhm  value_text: 3.3m  [TDK_B82732R]
L19  785 Ohm 3A  [INDC4532X17N[1812]]
L20  785 Ohm 3A  [INDC4532X17N[1812]]
L34  2A 100mOhm  value_text: 3m  [KEMET_SCxx-yyGJ_17X17MM]
L35  1k Ohm 0.5A  [INDC2012X110N[0805]]
LA5  600 Ohm 200mA  [FERCAV80P320X160X70-4]  (parts A,B,C,D of 4)
R77  3W 2512 1%  value_text: 0.001  [RESC6534X70[2512]_mOhm]
R81  value_text: 100k  [RESC1608X05AN[0603]]  (hidden comment: 1/10W 0603 1%)
R85  value_text: 220k  [RESC5025X60,2010,]  (hidden comment: 0.5W 2010 1%)
R99  0.5W 2010 1%  value_text: 3.3M  [RESC5025X60,2010,]
R100  value_text: 1k  [RESC1608X05AN[0603]]  (hidden comment: 1/10W 0603 1%)
R101  value_text: 1k  [RESC1608X05AN[0603]]  (hidden comment: 1/10W 0603 1%)
R102  value_text: 200  [RESC1608X05AN[0603]]  (hidden comment: 1/10W 0603 1%)
R103  value_text: 1k  [RESC1608X05AN[0603]]  (hidden comment: 1/10W 0603 1%)
R104  value_text: 1k  [RESC1608X05AN[0603]]  (hidden comment: 1/10W 0603 1%)
R215  0.33W 1210 1%  value_text: 4.7M  [RESC3225X70[1210]_HV]
RV3  manufacturer_pn: TMOV20RP300M  [LITTELFUSE_ITMOV_20MM]  (hidden comment: 300V MWV)
RV4  manufacturer_pn: TMOV20RP420M  [LITTELFUSE_ITMOV_20MM]  (hidden comment: 420V MWV)
RV5  manufacturer_pn: TMOV20RP420M  [LITTELFUSE_ITMOV_20MM]  (hidden comment: 420V MWV)
RV6  manufacturer_pn: TMOV20RP420M  [LITTELFUSE_ITMOV_20MM]  (hidden comment: 420V MWV)
TP3  TP TH  0.78mm  [TP_TH078H127P]  (value not drawn)  (no BOM)
TP21  manufacturer_pn: 5011  [KEYSTONE_5011]  (hidden comment: TP BLK)
TP33  TP SMD 1.5mm  [TP_SMD_Ø1.5mm]  (value not drawn)  (no BOM)
U7  LTV-814S  [DIP4_SMD]
U8  manufacturer_pn: ADE7912ARIZ  [SOIC127P1030X265-20N]  (hidden comment: ADE7912)

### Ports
MON (harness mon-data), PROT (harness prot)

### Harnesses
prot: LFUSED, NPROT, SET, RESET
mon-data: SCLK, MOSI, MISO, ~{CS}_PV, ADC_CLK, ~{DR}_PV, ~{CS}_MAINS, MOV_BAD, CAL

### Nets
3V3_ISO: C68.2 C69.2 C73.2 C76.2 R81.1 U8.19(VDD)
GND: C30.2 C39.2 C41.1 C42.1 GDT4.2 GDT5.2 JP3.1
GND_ISO: C43.2 C68.1 C69.1 C73.1 C76.1 C85.2 U7.3(Emitter) U8.11(GND) U8.20(GND)
GND_MON: C51.2 C52.2 C63.2 C66.2 C77.2 C78.2 C79.1 C80.2 C81.2 C82.2 C83.2 C84.1 C86.2 LA5.5 R100.1 R101.1 TP33.1 U8.2(GNDISO) U8.10(GNDISO)
L2: C39.1 CX2.1 L17.1 L18.2 L34.2 TP3.1
N2: C42.2 CX2.2 L18.3 L19.1 L34.3 TP21.1
Vcoil: K1.PLUS
L1: FC3.1 JP4.2
Lfiltered: C40.2 JP3.5 L17.2
LPROT: C30.1 K1.COM L18.1 L34.1 RV3.1
MON.ADC_CLK: U8.13(XTAL1) ; port MON.ADC_CLK
MON.~{CS}_MAINS: U8.18(~{CS}) ; port MON.~{CS}_MAINS
MON.MISO: U8.15(MISO) ; port MON.MISO
MON.MOSI: U8.16(MOSI) ; port MON.MOSI
MON.MOV_BAD: C43.1 R81.2 U7.4(Collector) ; port MON.MOV_BAD
MON.SCLK: U8.17(SCLK) ; port MON.SCLK
MON_IA+: C86.1 D36.A D37.K R104.2 U8.7(IP)
MON_IA-: C79.2 D36.K D37.A R103.1 U8.6(IM)
MON_LDO: C80.1 C81.1 U8.8(LDO)
MON_REF: C82.1 C83.1 U8.9(REF)
MON_V+: C77.1 D27.K D33.A R99.2 R100.2 R215.2 U8.4(V1P)
MON_V-: C78.1 D34.A D35.K R101.2 R102.2 U8.5(VM)
MOV1: RV4.3
MOV2: RV5.3
MOV3: RV6.3
MOV4: R85.2 RV3.3
N1: L20.2 LA5.2 R77.1
Nfiltered: C40.1 JP3.3 L19.2
Nin: JP4.1 L20.1
PROT.LFUSED: GDT3.1 K1.NO L7.2 L35.1 RV6.2 ; port PROT.LFUSED
PROT.NPROT: C41.2 L18.4 L34.4 LA5.3 LA5.4 R77.2 RV3.2 RV4.2 RV5.2 U7.2(Cathode) ; port PROT.NPROT
PROT.RESET: K1.RESET ; port PROT.RESET
PROT.SET: K1.SET ; port PROT.SET
VDDMON: C51.1 C52.1 C63.1 C66.1 U8.1(VDDISO)
NetC84_2: C84.2 C85.1
NetD27_A: D27.A D34.K
NetD33_K: D33.K D35.A
NetFC4_1: FC4.1 L7.1
NetGDT3_2: GDT3.2 RV4.1
NetGDT4_1: GDT4.1 RV5.1
NetGDT5_1: GDT5.1 RV6.1
NetL35_2: L35.2 R99.1 R215.1
NetLA5_6: LA5.6 R103.2
NetLA5_7: LA5.7 R104.1
NetR85_1: R85.1 U7.1(Anode)
NetR102_1: R102.1 U8.3(V2P)

Not connected (* = marked no-connect by the designer): LA5 1* 8*; U8 12(CO/~{DR})* 14(XTAL2)*

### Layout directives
net class Neut: GND_MON, MON_IA+, MON_IA-, MON_LDO, MON_REF, MON_V+, MON_V-, MOV1, MOV2, MOV4, N1, N2, Nfiltered, Nin, PROT.NPROT, VDDMON
net class LineProt: L2, Lfiltered, LPROT
net class LineUnprot: L1, MOV3, NetFC4_1, NetGDT3_2, NetGDT4_1, NetGDT5_1, NetL35_2, PROT.LFUSED

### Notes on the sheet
- protection relay
- voltage
- EMI filter
- (near JP4) Mains
- (near JP4) Input
- Connector to off-board
- AC/DC 24V supply
- Place on PCB as an alternate to
- (near L34) L18, but don't include on BOM.
- R215 provides same ratio as pre-R3.7, but only 600V capability.
- R99 utilizes the ADC range better and has 2kV capability.
- 200 ohm used as
- a jumper to short
- unused V2P to VM
- keep REF caps closer to IC than LDO
- Licensed under CERN-OHL-P v2, see cover page.
- caps, with 0.1uF closest.
- AC Mains Side
- Isolated side

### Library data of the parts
C30 C39 C41 C42 = CAP-00040: 2200pF 400VAC Ceramic Capacitor Y5V (F) Radial, Disc 0.354" Dia (9.00mm); manufacturer: Kemet; manufacturer_pn: C921U222MVVDBA7317; id: 139970; value: 2.2E-9; Key Parameters: X1/Y2 rating required, Y1 OK
C40 C84 C85 = CAP-00066: CAP CER 220PF 250VAC X7R 1808; manufacturer: Murata Electronics North America; manufacturer_pn: GA342DR7GF221KW02L; id: 162505; value: 2.2E-10; Key Parameters: X1/Y2 required, X7R is OK
C43 C51 C52 C73 C76 C80 C82 = CAP-00015: as C34 on sheet ACProtection
C63 C69 C81 C83 = CAP-00001: as C72 on sheet ACProtection
C66 C68 = CAP-00053: 1000pF ±5% 50V Ceramic Capacitor C0G, NP0 0603 (1608 Metric); manufacturer: Murata Electronics North America; manufacturer_pn: GRM1885C1H102JA01D; id: 147791; value: 1E-9; Key Parameters: V >= 25V
C77-C79 C86 = CAP-00000: as C36 on sheet ACProtection
CX2 = CAP-00037: 0.022µF Film Capacitor 275V 560V Polypropylene (PP), Metallized Radial 0.709" L x 0.197" W (18.00mm x 5.00mm); manufacturer: Kemet; manufacturer_pn: R46KI22200001K; id: 139960; value: 2.2E-8; Key Parameters: X2 rating required, X1 even better
D27 D33-D37 = DIO-00004: as D19-D22 on sheet ACProtection
F2 = FUSE-00008: FUSE CERM 2A 500VAC 400VDC 5X20 slow blow; manufacturer_pn: 0477002.MXP; manufacturer: Littelfuse Inc.; id: 169738
FC3 FC4 = CONN-00079: Fuse Clip 10A 1 Circuit Cartridge PCB 5x20mm; manufacturer_pn: 0751.0110; manufacturer: Schurter Inc.; id: 141097
GDT3 = PROT-00002: Gas Discharge Tube 1500V 5000A (5kA) 2 Pole Through Hole; manufacturer: Littelfuse Inc.; id: 141106; value: 1500
GDT4 GDT5 = PROT-00003: Gas Discharge Tube 2500V 5000A (5kA) 2 Pole Through Hole; manufacturer: Littelfuse Inc.; id: 141107; value: 2500
JP3 = CONN-00069: 5 Positions Header, Unshrouded Connector 0.312" (7.92mm) Through Hole Tin; manufacturer_pn: 1-1123724-3; manufacturer: TE Connectivity AMP Connectors; id: 140462
JP4 = CONN-00078: 2 Positions Header, Shrouded Connector 0.250" (6.35mm) Through Hole Tin, MLX series; manufacturer_pn: 0432550059; manufacturer: Molex, LLC; id: 141096
K1 = RELAY-00002: General Purpose Relay SPST Latching 2 coil 12V 20A RTS3LF12; manufacturer: TE Connectivity relay divisions; manufacturer_pn: 2-1415898-5; id: 141088
L7 L17 L19 L20 = FER-00006: FERRITE BEAD 785 OHM 1812 1LN 50mohm; manufacturer: Wurth Electronics Inc; manufacturer_pn: 742792515; value_text: 785; id: 140504; value: 785
L18 = IND-00019: 3.3mH @ 10kHz 2 Line Common Mode Choke Through Hole 2.2A DCR 110 mOhm; manufacturer: EPCOS (TDK); manufacturer_pn: B82732R2222B030; id: 169929; value: 0.0033
L34 = IND-00020: 3mH @ 100kHz 2 Line Common Mode Choke Through Hole 2A DCR 100 mOhm; manufacturer_pn: SC-02-30GJ; manufacturer: Kemet; id: 169931; value: 0.003
L35 = FER-00005: FERRITE BEAD 1 KOHM 0805 1LN 0.28 ohm; manufacturer: Murata Electronics North America; manufacturer_pn: BLM21AG102SN1D; id: 137114; value: 1000
LA5 = FER-00009: as LA4 on sheet DCPower
R77 = RES-00044: as R25 on sheet DCPower
R81 = RES-00112: as R62 on sheet ACProtection
R85 = RES-00128: 220 kOhms ±1% 0.5W, 1/2W Chip Resistor 2010 (5025 Metric) High Voltage Thick Film; manufacturer: Bourns Inc.; manufacturer_pn: CHV2010-FX-2203ELF; id: 196949; value: 220000; Key Parameters: 5% OK
R99 = RES-00125: as R91 on sheet ACProtection
R100 R101 R103 R104 = RES-00113: as R52 on sheet ACProtection
R102 = RES-00019: as R70 on sheet ACProtection
R215 = RES-00127: 4.7 MOhms ±1% 0.333W, 1/3W Chip Resistor 1210 (3225 Metric) Automotive AEC-Q200, High Voltage Thick Film; manufacturer_pn: KTR25JZPF4704; manufacturer: Rohm Semiconductor; id: 196948; value: 4700000
RV3 = PROT-00001: VARISTOR 470V 10KA DISC 20MM; manufacturer: Littelfuse Inc.; id: 141105; value: 300
RV4-RV6 = PROT-00000: VARISTOR 680V 10KA DISC 20MM; manufacturer: Littelfuse Inc.; id: 141104; value: 420
TP3 = NOBOM-00007: as TP27 on sheet DCPower
TP21 = CONN-00028: as TP11 on sheet DCPower
TP33 = NOBOM-00008: as TP13 on sheet ACProtection
U7 = ICXCV-00005: Optoisolator Transistor Output 5000Vrms 1 Channel 4-SMD; manufacturer: Lite-On Inc.; id: 141327
U8 = ICANA-00004: ADC, Energy Measurement 24 bit SPI 20-SOIC-RI; manufacturer: Analog Devices Inc.; id: 138317

## Sheet AuxOutput.SchDoc
size B; SheetNumber: 7; nhSheetName: Auxiliary Outputs
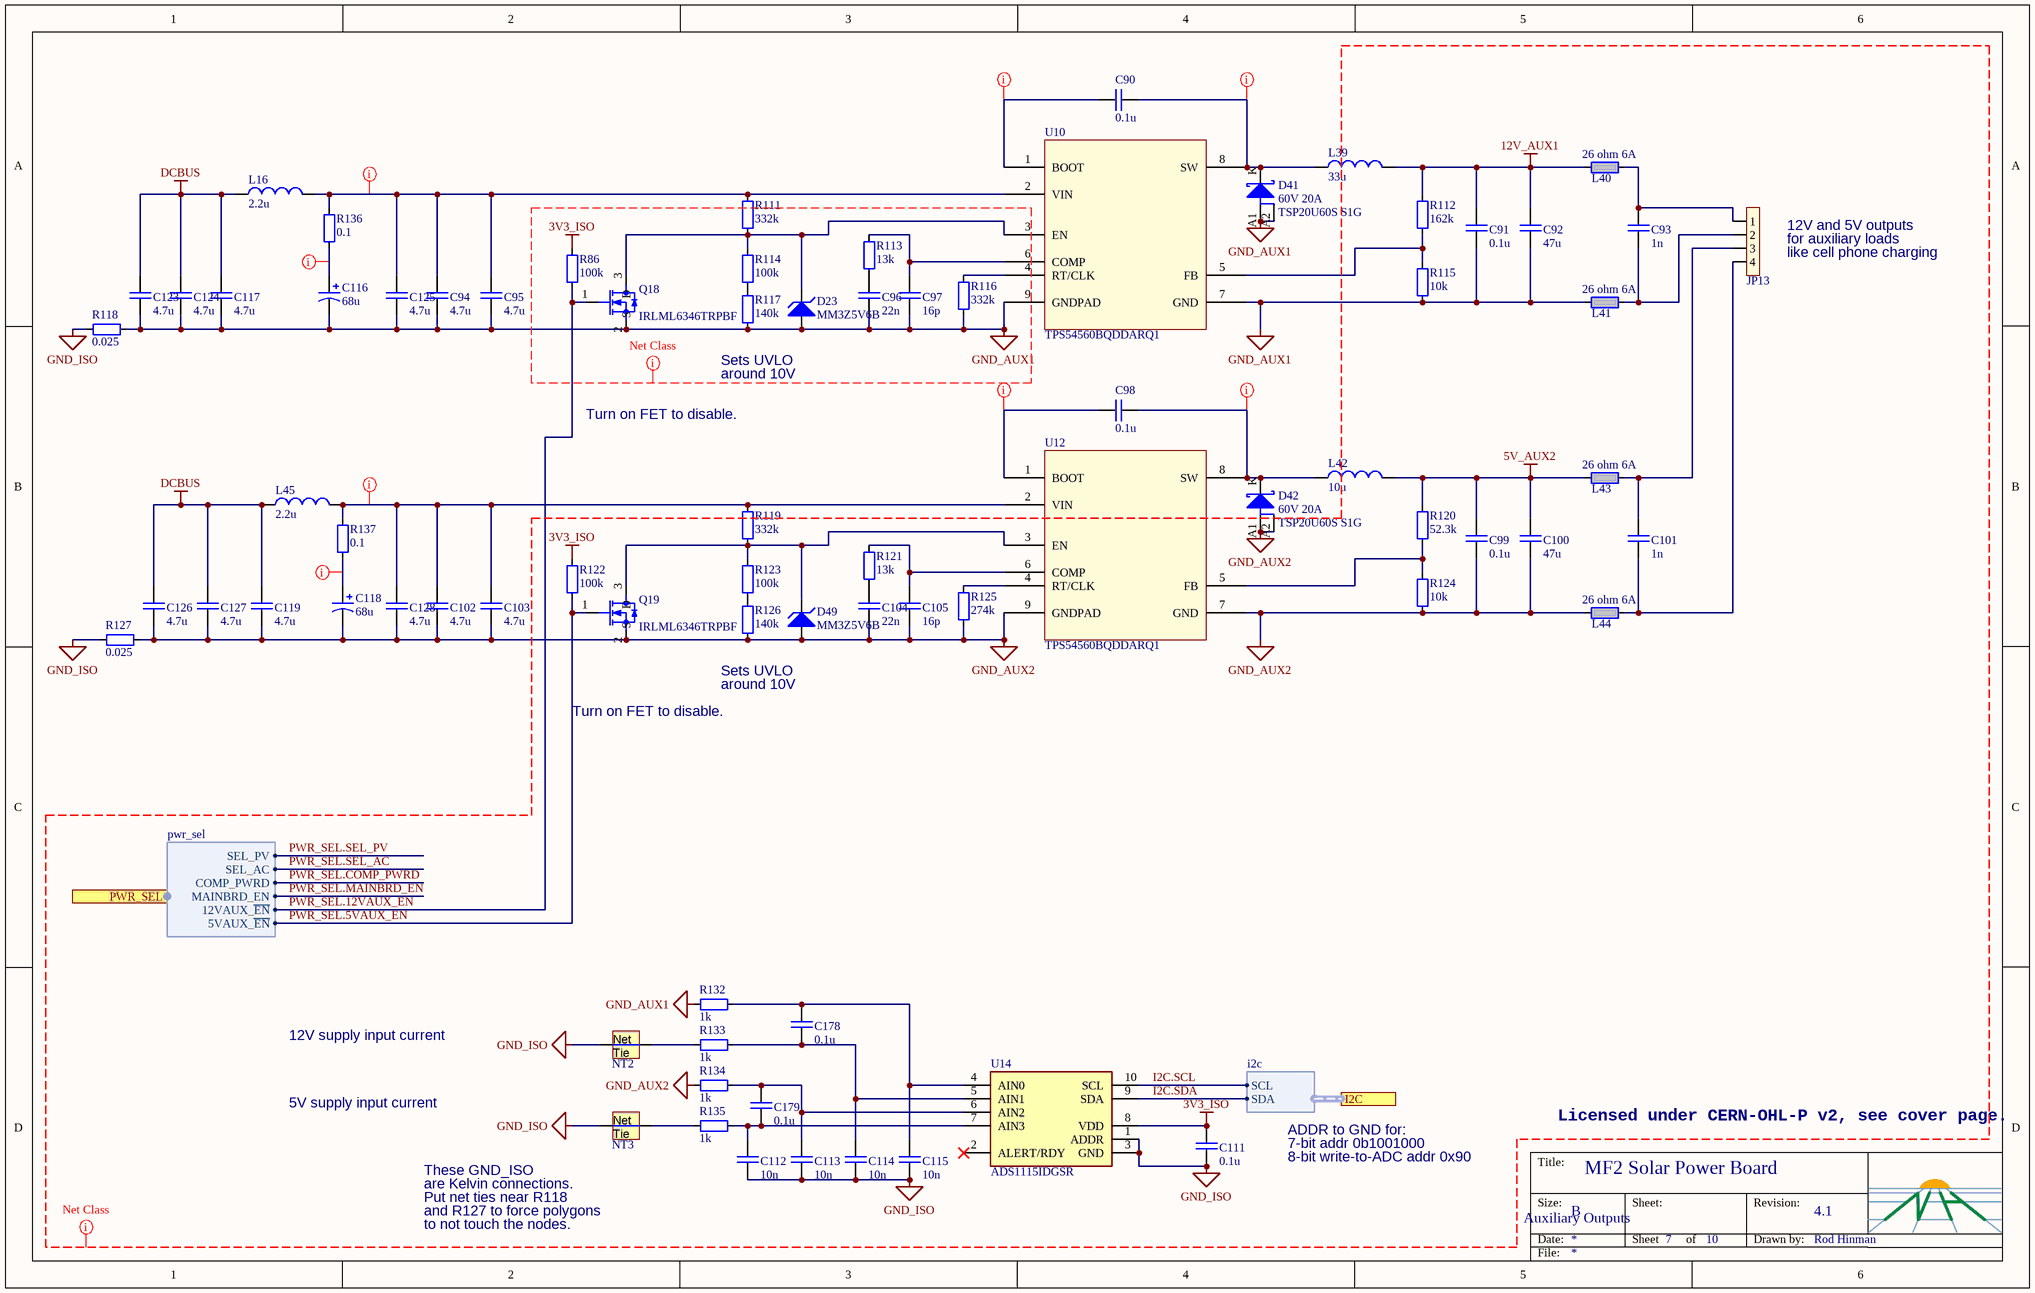
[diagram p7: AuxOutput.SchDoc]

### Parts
C90  value_text: 0.1u  [CAPC1608X09N[0603]]  (hidden comment: 50V X7R 0603)
C91  value_text: 0.1u  [CAPC1608X09N[0603]]  (hidden comment: 50V X7R 0603)
C92  value_text: 47u  [CAPC3225X270]  (hidden comment: 16V  X5R 1210)
C93  value_text: 1n  [CAPC1608X09N[0603]]  (hidden comment: 50V C0G 0603)
C94  value_text: 4.7u  [CAPC3225X270]  (hidden comment: 100V X5R 1210)
C95  value_text: 4.7u  [CAPC3225X270]  (hidden comment: 100V X5R 1210)
C96  value_text: 22n  [CAPC1608X09N[0603]]  (hidden comment: 50V X7R 0603)
C97  value_text: 16p  [CAPC1608X09N[0603]]  (hidden comment: 50V C0G 0603)
C98  value_text: 0.1u  [CAPC1608X09N[0603]]  (hidden comment: 50V X7R 0603)
C99  value_text: 0.1u  [CAPC1608X09N[0603]]  (hidden comment: 50V X7R 0603)
C100  value_text: 47u  [CAPC3225X270]  (hidden comment: 16V  X5R 1210)
C101  value_text: 1n  [CAPC1608X09N[0603]]  (hidden comment: 50V C0G 0603)
C102  value_text: 4.7u  [CAPC3225X270]  (hidden comment: 100V X5R 1210)
C103  value_text: 4.7u  [CAPC3225X270]  (hidden comment: 100V X5R 1210)
C104  value_text: 22n  [CAPC1608X09N[0603]]  (hidden comment: 50V X7R 0603)
C105  value_text: 16p  [CAPC1608X09N[0603]]  (hidden comment: 50V C0G 0603)
C111  value_text: 0.1u  [CAPC1608X09N[0603]]  (hidden comment: 50V X7R 0603)
C112  value_text: 10n  [CAPC1608X09N[0603]]  (hidden comment: 50V C0G 0603)
C113  value_text: 10n  [CAPC1608X09N[0603]]  (hidden comment: 50V C0G 0603)
C114  value_text: 10n  [CAPC1608X09N[0603]]  (hidden comment: 50V C0G 0603)
C115  value_text: 10n  [CAPC1608X09N[0603]]  (hidden comment: 50V C0G 0603)
C116  value_text: 68u  [CAPAE1300X1350D1370DD420L475N]  (hidden comment: 80V Can 20% 320mO)
C117  value_text: 4.7u  [CAPC3225X270]  (hidden comment: 100V X5R 1210)
C118  value_text: 68u  [CAPAE1300X1350D1370DD420L475N]  (hidden comment: 80V Can 20% 320mO)
C119  value_text: 4.7u  [CAPC3225X270]  (hidden comment: 100V X5R 1210)
C123  value_text: 4.7u  [CAPC3225X270]  (hidden comment: 100V X5R 1210)
C124  value_text: 4.7u  [CAPC3225X270]  (hidden comment: 100V X5R 1210)
C125  value_text: 4.7u  [CAPC3225X270]  (hidden comment: 100V X5R 1210)
C126  value_text: 4.7u  [CAPC3225X270]  (hidden comment: 100V X5R 1210)
C127  value_text: 4.7u  [CAPC3225X270]  (hidden comment: 100V X5R 1210)
C128  value_text: 4.7u  [CAPC3225X270]  (hidden comment: 100V X5R 1210)
C178  value_text: 0.1u  [CAPC1608X09N[0603]]  (hidden comment: 50V X7R 0603)
C179  value_text: 0.1u  [CAPC1608X09N[0603]]  (hidden comment: 50V X7R 0603)
D23  manufacturer_pn: MM3Z5V6B  [SOD-323F]  (hidden comment: 5.6V 200mW)
D41  60V 20A  manufacturer_pn: TSP20U60S S1G  [TO-277_Z3N]
D42  60V 20A  manufacturer_pn: TSP20U60S S1G  [TO-277_Z3N]
D49  manufacturer_pn: MM3Z5V6B  [SOD-323F]  (hidden comment: 5.6V 200mW)
JP13  1x4 3.96mm  [AMP_1-1123723-4]  (value not drawn)
L16  value_text: 2.2u  [INDUCTOR-BOURNS_SRN6045]  (hidden comment: 6A 15mOhm)
L39  value_text: 33u  [INDUCTOR_VISHAY_IHLP-6767]  (hidden comment: 9A 37mOhm)
L40  26 ohm 6A  [FER1608X100[0603]]
L41  26 ohm 6A  [FER1608X100[0603]]
L42  value_text: 10u  [INDUCTOR-BOURNS_SRR1280]  (hidden comment: 6A 19.5mOhm)
L43  26 ohm 6A  [FER1608X100[0603]]
L44  26 ohm 6A  [FER1608X100[0603]]
L45  value_text: 2.2u  [INDUCTOR-BOURNS_SRN6045]  (hidden comment: 6A 15mOhm)
NT2  Net Tie  [NETTIE_0.254mm_NOPADS]  (value not drawn)  (net tie, no BOM)
NT3  Net Tie  [NETTIE_0.254mm_NOPADS]  (value not drawn)  (net tie, no BOM)
Q18  manufacturer_pn: IRLML6346TRPBF  [SOT23-3]  (hidden comment: N-CH 30V 3.4A)
Q19  manufacturer_pn: IRLML6346TRPBF  [SOT23-3]  (hidden comment: N-CH 30V 3.4A)
R86  value_text: 100k  [RESC1608X05AN[0603]]  (hidden comment: 1/10W 0603 1%)
R111  value_text: 332k  [RESC1608X05AN[0603]]  (hidden comment: 1/10W 0603 1%)
R112  value_text: 162k  [RESC1608X05AN[0603]]  (hidden comment: 1/10W 0603 1%)
R113  value_text: 13k  [RESC1608X05AN[0603]]  (hidden comment: 1/10W 0603 1%)
R114  value_text: 100k  [RESC1608X05AN[0603]]  (hidden comment: 1/10W 0603 1%)
R115  value_text: 10k  [RESC1608X05AN[0603]]  (hidden comment: 1/10W 0603 1%)
R116  value_text: 332k  [RESC1608X05AN[0603]]  (hidden comment: 1/10W 0603 1%)
R117  value_text: 140k  [RESC1608X05AN[0603]]  (hidden comment: 1/10W 0603 1%)
R118  value_text: 0.025  [RESC6534X70[2512]]  (hidden comment: 3W 2512 1%)
R119  value_text: 332k  [RESC1608X05AN[0603]]  (hidden comment: 1/10W 0603 1%)
R120  value_text: 52.3k  [RESC1608X05AN[0603]]  (hidden comment: 1/10W 0603 1%)
R121  value_text: 13k  [RESC1608X05AN[0603]]  (hidden comment: 1/10W 0603 1%)
R122  value_text: 100k  [RESC1608X05AN[0603]]  (hidden comment: 1/10W 0603 1%)
R123  value_text: 100k  [RESC1608X05AN[0603]]  (hidden comment: 1/10W 0603 1%)
R124  value_text: 10k  [RESC1608X05AN[0603]]  (hidden comment: 1/10W 0603 1%)
R125  value_text: 274k  [RESC1608X05AN[0603]]  (hidden comment: 1/10W 0603 1%)
R126  value_text: 140k  [RESC1608X05AN[0603]]  (hidden comment: 1/10W 0603 1%)
R127  value_text: 0.025  [RESC6534X70[2512]]  (hidden comment: 3W 2512 1%)
R132  value_text: 1k  [RESC1608X05AN[0603]]  (hidden comment: 1/10W 0603 1%)
R133  value_text: 1k  [RESC1608X05AN[0603]]  (hidden comment: 1/10W 0603 1%)
R134  value_text: 1k  [RESC1608X05AN[0603]]  (hidden comment: 1/10W 0603 1%)
R135  value_text: 1k  [RESC1608X05AN[0603]]  (hidden comment: 1/10W 0603 1%)
R136  value_text: 0.1  [RESC1005X40[0402]]  (hidden comment: 1/16W 0402)
R137  value_text: 0.1  [RESC1005X40[0402]]  (hidden comment: 1/16W 0402)
U10  manufacturer_pn: TPS54560BQDDARQ1  [SOIC127P600X170_HS-9N]  (hidden comment: 5A)
U12  manufacturer_pn: TPS54560BQDDARQ1  [SOIC127P600X170_HS-9N]  (hidden comment: 5A)
U14  manufacturer_pn: ADS1115IDGSR  [TSSOP50P490X110-10N]  (hidden comment: ADS1115)

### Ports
I2C (harness i2c), PWR_SEL (harness pwr_sel)

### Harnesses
i2c: SDA, SCL
pwr_sel: SEL_PV, SEL_AC, COMP_PWRD, 12VAUX_~{EN}, 5VAUX_~{EN}, MAINBRD_EN

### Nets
3V3_ISO: C111.1 R86.2 R122.2 U14.8(VDD)
5V_AUX2: C99.1 C100.1 L42.2 L43.1 R120.1
12V_AUX1: C91.1 C92.1 L39.2 L40.1 R112.1
DCBUS: C117.1 C119.1 C123.1 C124.1 C126.1 C127.1 L16.1 L45.1
GND_AUX1: C91.2 C92.2 C94.2 C95.2 C96.2 C97.2 C116.- C117.2 C123.2 C124.2 C125.2 D23.A D41.A1 D41.A2 L41.1 Q18.2(S) R115.2 R116.2 R117.2 R118.2 R132.1 U10.7(GND) U10.9(GNDPAD)
GND_AUX2: C99.2 C100.2 C102.2 C103.2 C104.2 C105.2 C118.- C119.2 C126.2 C127.2 C128.2 D42.A1 D42.A2 D49.A L44.1 Q19.2(S) R124.2 R125.2 R126.2 R127.2 R134.1 U12.7(GND) U12.9(GNDPAD)
GND_ISO: C111.2 C112.2 C113.2 C114.2 C115.2 NT2.1 NT3.1 R118.1 R127.1 U14.1(ADDR) U14.3(GND)
I2C.SCL: U14.10(SCL) ; port I2C.SCL
I2C.SDA: U14.9(SDA) ; port I2C.SDA
PWR_SEL.5VAUX_~{EN}: Q19.1(G) R122.1 ; port PWR_SEL.5VAUX_~{EN}
PWR_SEL.12VAUX_~{EN}: Q18.1(G) R86.1 ; port PWR_SEL.12VAUX_~{EN}
NetC90_1: C90.1 U10.1(BOOT)
NetC90_2: C90.2 D41.K L39.1 U10.8(SW)
NetC93_1: C93.1 JP13.1 L40.2
NetC93_2: C93.2 JP13.2 L41.2
NetC94_1: C94.1 C95.1 C125.1 L16.2 R111.1 R136.1 U10.2(VIN)
NetC96_1: C96.1 R113.2
NetC97_1: C97.1 R113.1 U10.6(COMP)
NetC98_1: C98.1 U12.1(BOOT)
NetC98_2: C98.2 D42.K L42.1 U12.8(SW)
NetC101_1: C101.1 JP13.3 L43.2
NetC101_2: C101.2 JP13.4 L44.2
NetC102_1: C102.1 C103.1 C128.1 L45.2 R119.1 R137.1 U12.2(VIN)
NetC104_1: C104.1 R121.2
NetC105_1: C105.1 R121.1 U12.6(COMP)
NetC112_1: C112.1 C179.2 R135.2 U14.7(AIN3)
NetC113_1: C113.1 C179.1 R134.2 U14.6(AIN2)
NetC114_1: C114.1 C178.2 R133.2 U14.5(AIN1)
NetC115_1: C115.1 C178.1 R132.2 U14.4(AIN0)
NetC116_+: C116.+ R136.2
NetC118_+: C118.+ R137.2
NetD23_K: D23.K Q18.3(D) R111.2 R114.2 U10.3(EN)
NetD49_K: D49.K Q19.3(D) R119.2 R123.2 U12.3(EN)
NetNT2_2: NT2.2 R133.1
NetNT3_2: NT3.2 R135.1
NetR112_2: R112.2 R115.1 U10.5(FB)
NetR114_1: R114.1 R117.1
NetR116_1: R116.1 U10.4(RT/CLK)
NetR120_2: R120.2 R124.1 U12.5(FB)
NetR123_1: R123.1 R126.1
NetR125_1: R125.1 U12.4(RT/CLK)

Not connected (* = marked no-connect by the designer): U14 2(ALERT/RDY)*

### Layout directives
net class SELV: 3V3_ISO, 5V_AUX2, 12V_AUX1, DCBUS, GND_AUX1, GND_AUX2, GND_ISO, I2C.SCL, I2C.SDA, PWR_SEL.5VAUX_~{EN}, PWR_SEL.12VAUX_~{EN}, PWR_SEL.COMP_PWRD, PWR_SEL.MAINBRD_EN, PWR_SEL.SEL_AC, PWR_SEL.SEL_PV
net class PVPOS: NetC90_1, NetC90_2, NetC94_1, NetC98_1, NetC98_2, NetC102_1, NetC116_+, NetC118_+

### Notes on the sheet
- (near JP13) 12V and 5V outputs
- (near JP13) for auxiliary loads
- (near JP13) like cell phone charging
- Sets UVLO
- Turn on FET to disable.
- around 10V
- 12V supply input current
- 5V supply input current
- These GND_ISO
- 7-bit addr 0b1001000
- 8-bit write-to-ADC addr 0x90
- ADDR to GND for:
- Licensed under CERN-OHL-P v2, see cover page.
- are Kelvin connections.
- Put net ties near R118
- and R127 to force polygons
- to not touch the nodes.

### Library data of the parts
C90 C91 C98 C99 C111 C178 C179 = CAP-00001: as C72 on sheet ACProtection
C92 C100 = CAP-00050: 47µF ±20% 16V Ceramic Capacitor X5R 1210 (3225 Metric); manufacturer: Murata Electronics North America; manufacturer_pn: GRM32ER61C476ME15L; id: 147646; value: 4.7E-5; Key Parameters: V >= 16V
C93 C101 = CAP-00053: as C66 on sheet ACPower
C94 C95 C102 C103 C117 C119 C123-C128 = CAP-00075: 4.7µF ±10% 100V Ceramic Capacitor X5R 1210 (3225 Metric); manufacturer: Taiyo Yuden; manufacturer_pn: HMK325BJ475KM-PE; id: 171762; value: 4.7E-6; Key Parameters: V >= 50V preferred, 25V possible
C96 C104 = CAP-00035: 0.022µF 50V Ceramic Capacitor X7R 0603 (1608 Metric) 0.063" L x 0.031" W (1.60mm x 0.80mm); manufacturer: Murata Electronics North America; manufacturer_pn: GRM188R71H223KA01D; id: 137516; value: 2.2E-8; Key Parameters: v >= 16V
C97 C105 = CAP-00051: 16pF ±5% 50V Ceramic Capacitor C0G, NP0 0603 (1608 Metric); manufacturer: Murata Electronics North America; manufacturer_pn: GRM1885C1H160JA01D; id: 147785; value: 1.6E-11; Key Parameters: V >= 16V
C112-C115 = CAP-00027: as C13 on sheet DCPower
C116 C118 = CAP-00072: 68µF 80V Aluminum Electrolytic Capacitors Radial, Can - SMD 5000 Hrs @ 105°C; manufacturer: Panasonic Electronic Components; manufacturer_pn: EEV-FK1K680Q; id: 169906; value: 6.8E-5; Key Parameters: V >= 50V preferred, 25V possible
D23 D49 = DIO-00042: Zener Diode 5.6V 200mW ±2% Surface Mount SOD-323F; manufacturer: ON Semiconductor; id: 363924
D41 D42 = DIO-00037: Diode Schottky 60V 20A Surface Mount TO-277A (SMPC); manufacturer: Taiwan Semiconductor Corporation; id: 193255
JP13 = CONN-00068: 4 Positions Header, Unshrouded Connector 0.156" (3.96mm) Through Hole Tin (GRN); manufacturer_pn: 6-1123723-4; manufacturer: TE Connectivity AMP Connectors; id: 140461
L16 L45 = IND-00023: 2.2µH Semi-Shielded Wirewound Inductor 6A 15 mOhm Nonstandard; manufacturer_pn: SRN6045TA-2R2Y; manufacturer: Bourns Inc.; id: 170438; value: 2.2E-6
L39 = IND-00013: 33µH Shielded Molded Inductor 10.7A 37 mOhm Max Nonstandard; manufacturer_pn: IHLP6767GZER330M11; manufacturer: Vishay Dale; id: 147638; value: 3.3E-5
L40 L41 L43 L44 = FER-00008: FERRITE BEAD 26 OHM 0603 1LN 7 mohm; manufacturer_pn: MPZ1608S260ATAH0; manufacturer: TDK Corporation; value_text: 26; id: 159931; value: 26
L42 = IND-00008: 10µH Shielded Wirewound Inductor 6A 19.5 mOhm Max Nonstandard; manufacturer_pn: SRR1280-100M; manufacturer: Bourns Inc.; id: 140505; value: 1E-5
NT2 NT3 = NOBOM-00016: Net tie 0.254mm no pads; manufacturer: New Horizons; id: 178547
Q18 Q19 = FET-00002: as Q9 on sheet DCPower
R86 R114 R122 R123 = RES-00112: as R62 on sheet ACProtection
R111 R116 R119 = RES-00064: RES SMD 332K OHM 1% 1/10W 0603; manufacturer_pn: ERJ-3EKF3323V; manufacturer: Panasonic Electronic Components; id: 147650; value: 332000; Key Parameters: 1% required
R112 = RES-00154: 162 kOhms ±1% 0.1W, 1/10W Chip Resistor 0603 (1608 Metric) Automotive AEC-Q200 Thick Film; manufacturer_pn: ERJ-3EKF1623V; manufacturer: Panasonic Electronic Components; id: 316322; value: 162000; Key Parameters: 1% required
R113 R121 = RES-00062: RES SMD 13.0K OHM 1% 1/10W 0603; manufacturer_pn: ERJ-3EKF1302V; manufacturer: Panasonic Electronic Components; id: 147648; value: 13000; Key Parameters: 1% required
R115 R124 = RES-00107: as R37 on sheet DCPower
R117 R126 = RES-00063: RES SMD 140K OHM 1% 1/10W 0603; manufacturer_pn: ERJ-3EKF1403V; manufacturer: Panasonic Electronic Components; id: 147649; value: 140000; Key Parameters: 1% required
R118 R127 = RES-00045: RES SMD 0.025 OHM 1% 3W 2512; manufacturer_pn: CRA2512-FZ-R025ELF; manufacturer: Bourns Inc.; id: 140451; value: 0.025; Key Parameters: 1% required
R120 = RES-00031: RES SMD 52.3K OHM 1% 1/10W 0603; manufacturer_pn: ERJ-3EKF5232V; manufacturer: Panasonic Electronic Components; id: 137109; value: 52300; Key Parameters: 1% required
R125 = RES-00096: RES SMD 274K OHM 1% 1/10W 0603; manufacturer_pn: ERJ-3EKF2743V; manufacturer: Panasonic Electronic Components; id: 169761; value: 274000; Key Parameters: 1% required
R132-R135 = RES-00113: 1 kOhms ±1% 0.1W, 1/10W Chip Resistor 0603 (1608 Metric) Automotive AEC-Q200 Thick Film; manufacturer_pn: ERJ-3EKF1001V; manufacturer: Panasonic Electronic Components; id: 185365; value: 1000; Key Parameters: 1% required
R136 R137 = RES-00097: RES SMD 0.1 OHM 1% 1/6W 0402; manufacturer_pn: ERJ-2BSFR10X; manufacturer: Panasonic Electronic Components; id: 169912; value: 0.1; Key Parameters: 5% OK
U10 U12 = ICPWR-00044: Buck, Split Rail Switching Regulator IC Positive Adjustable 0.8V 1 Output 5A 8-PowerSOIC (0.154", 3.90mm Width); manufacturer: Texas Instruments; id: 363923
U14 = ICANA-00023: 16 Bit Analog to Digital Converter 2, 4 Input 1 Sigma-Delta 10-VSSOP; manufacturer: Texas Instruments; id: 169397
